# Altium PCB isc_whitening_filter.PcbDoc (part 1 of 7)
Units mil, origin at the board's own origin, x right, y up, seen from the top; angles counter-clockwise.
Board outline 8440 x 7000 mil, 6 copper layers (Top Layer, MidLayer1, InternalPlane1, Internal Plane 3, InternalPlane2, Bottom Layer); 550 components, 434 nets, 2189 pads, 806 vias.
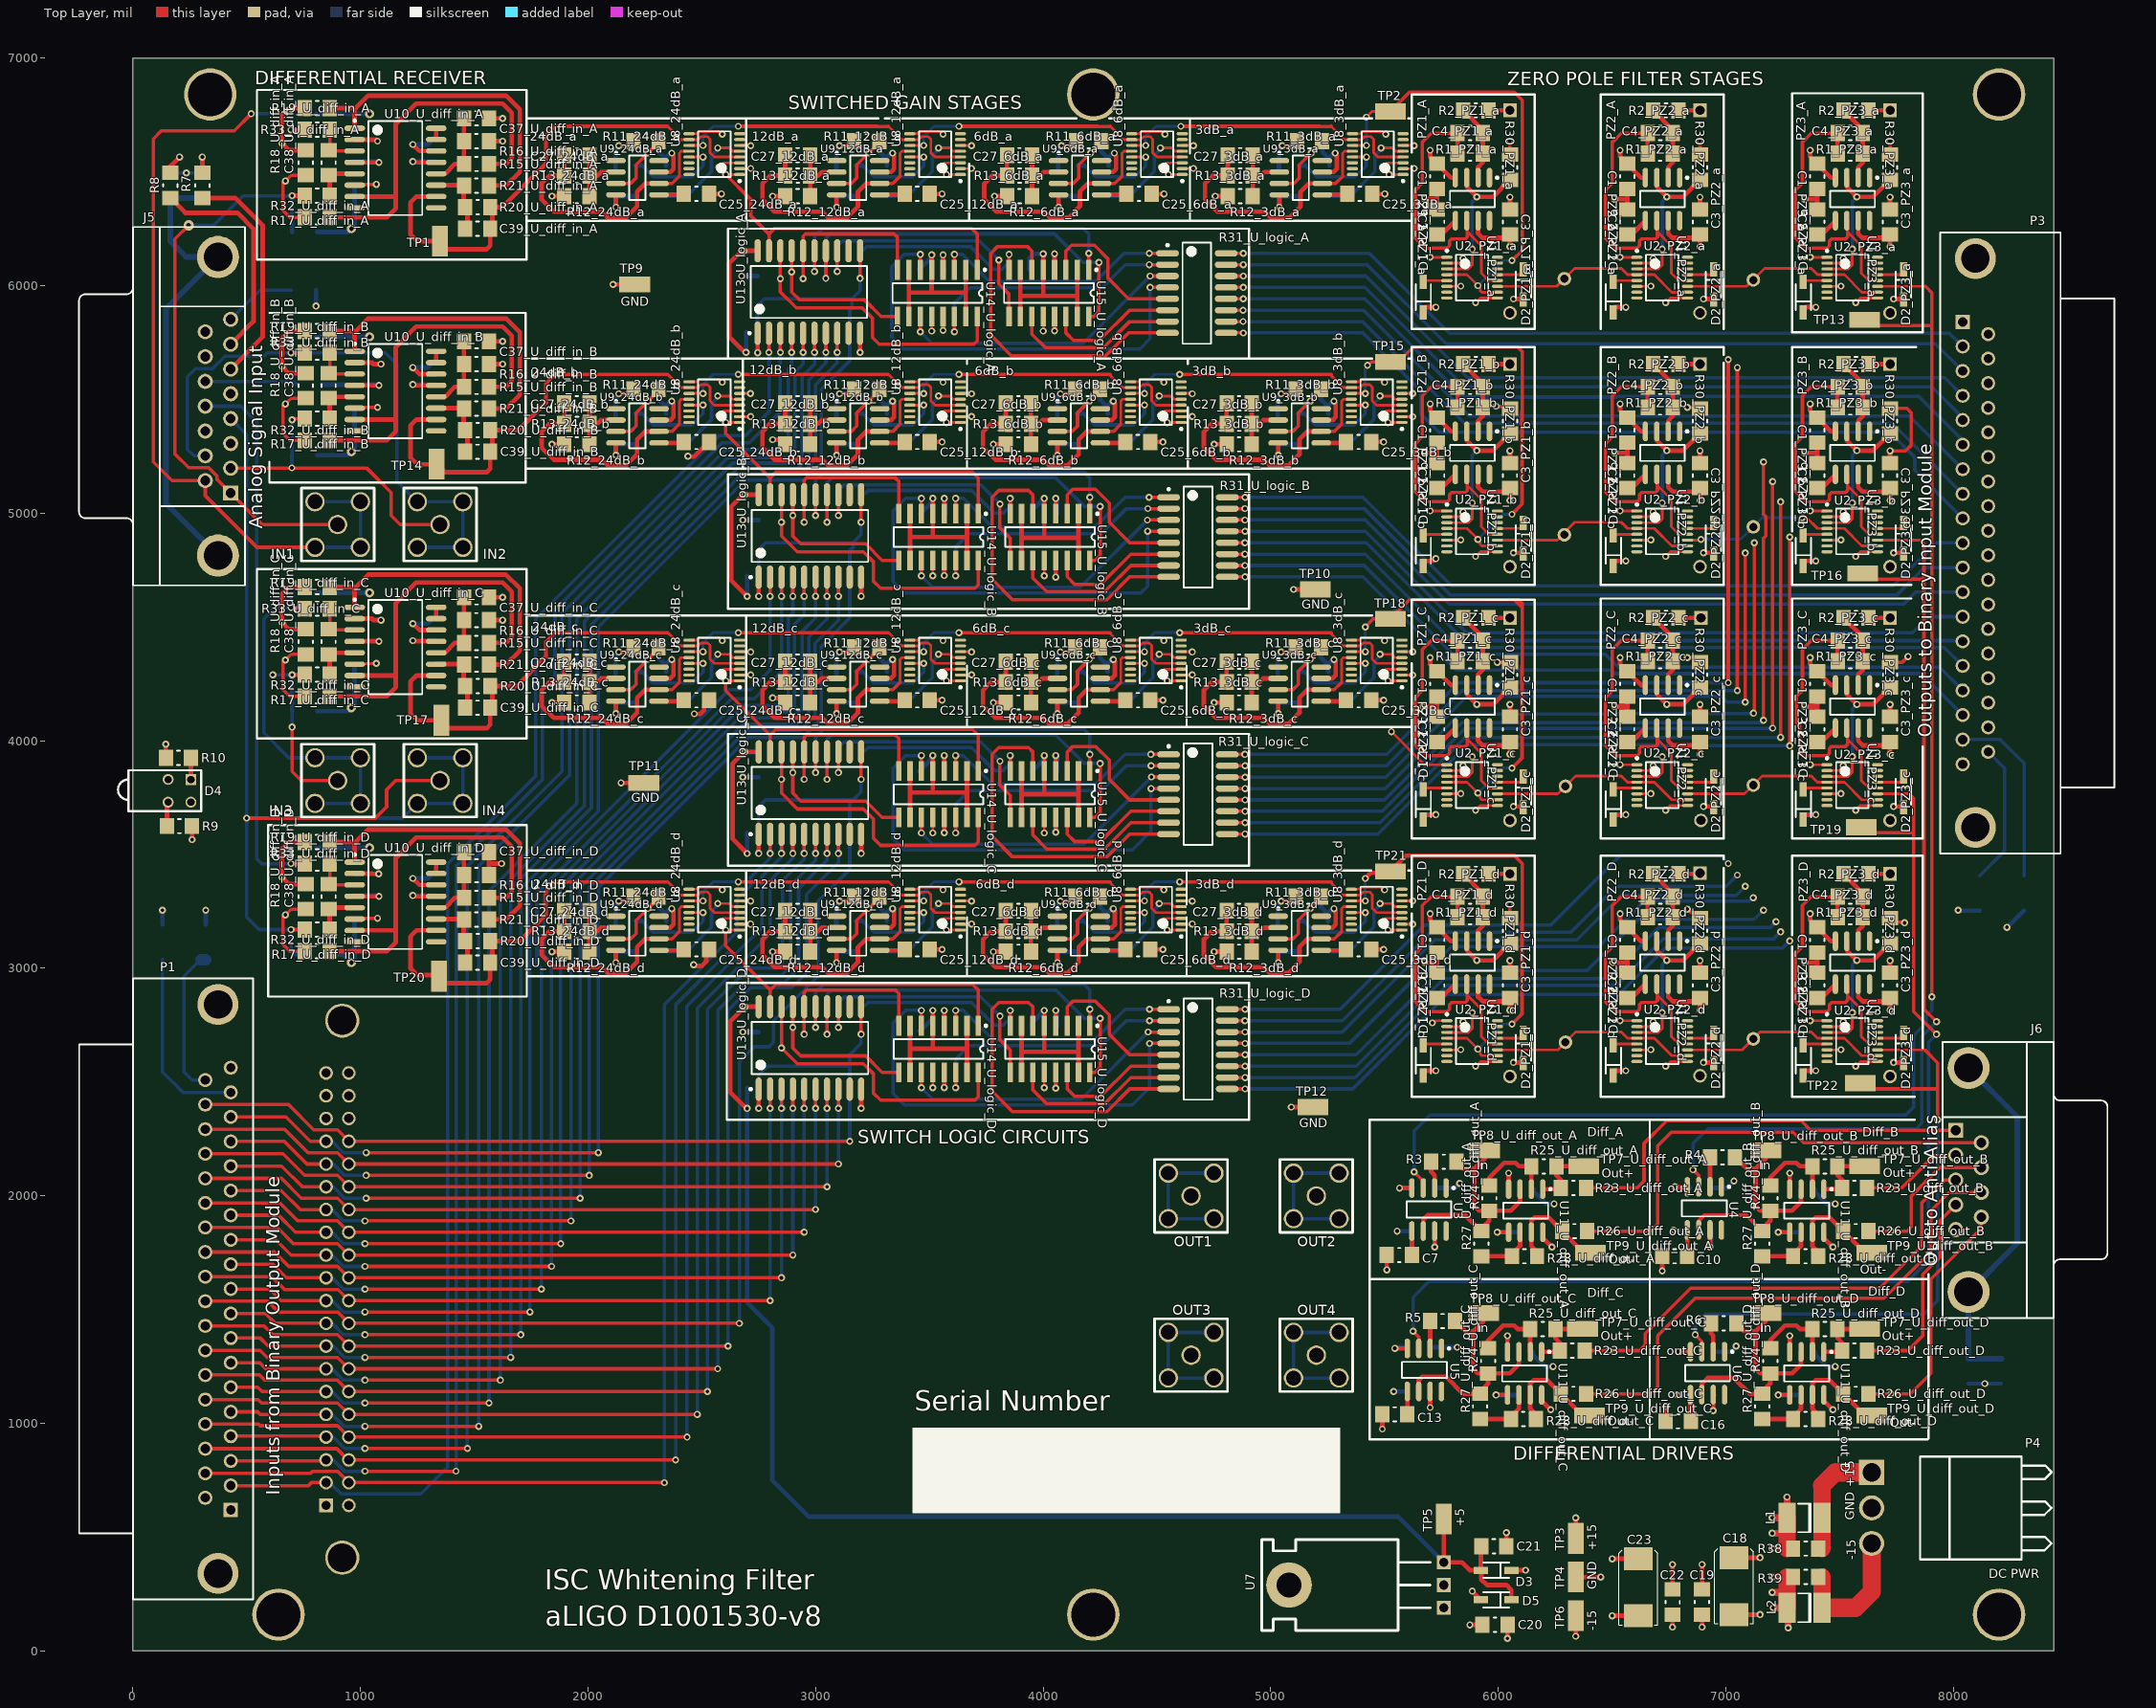
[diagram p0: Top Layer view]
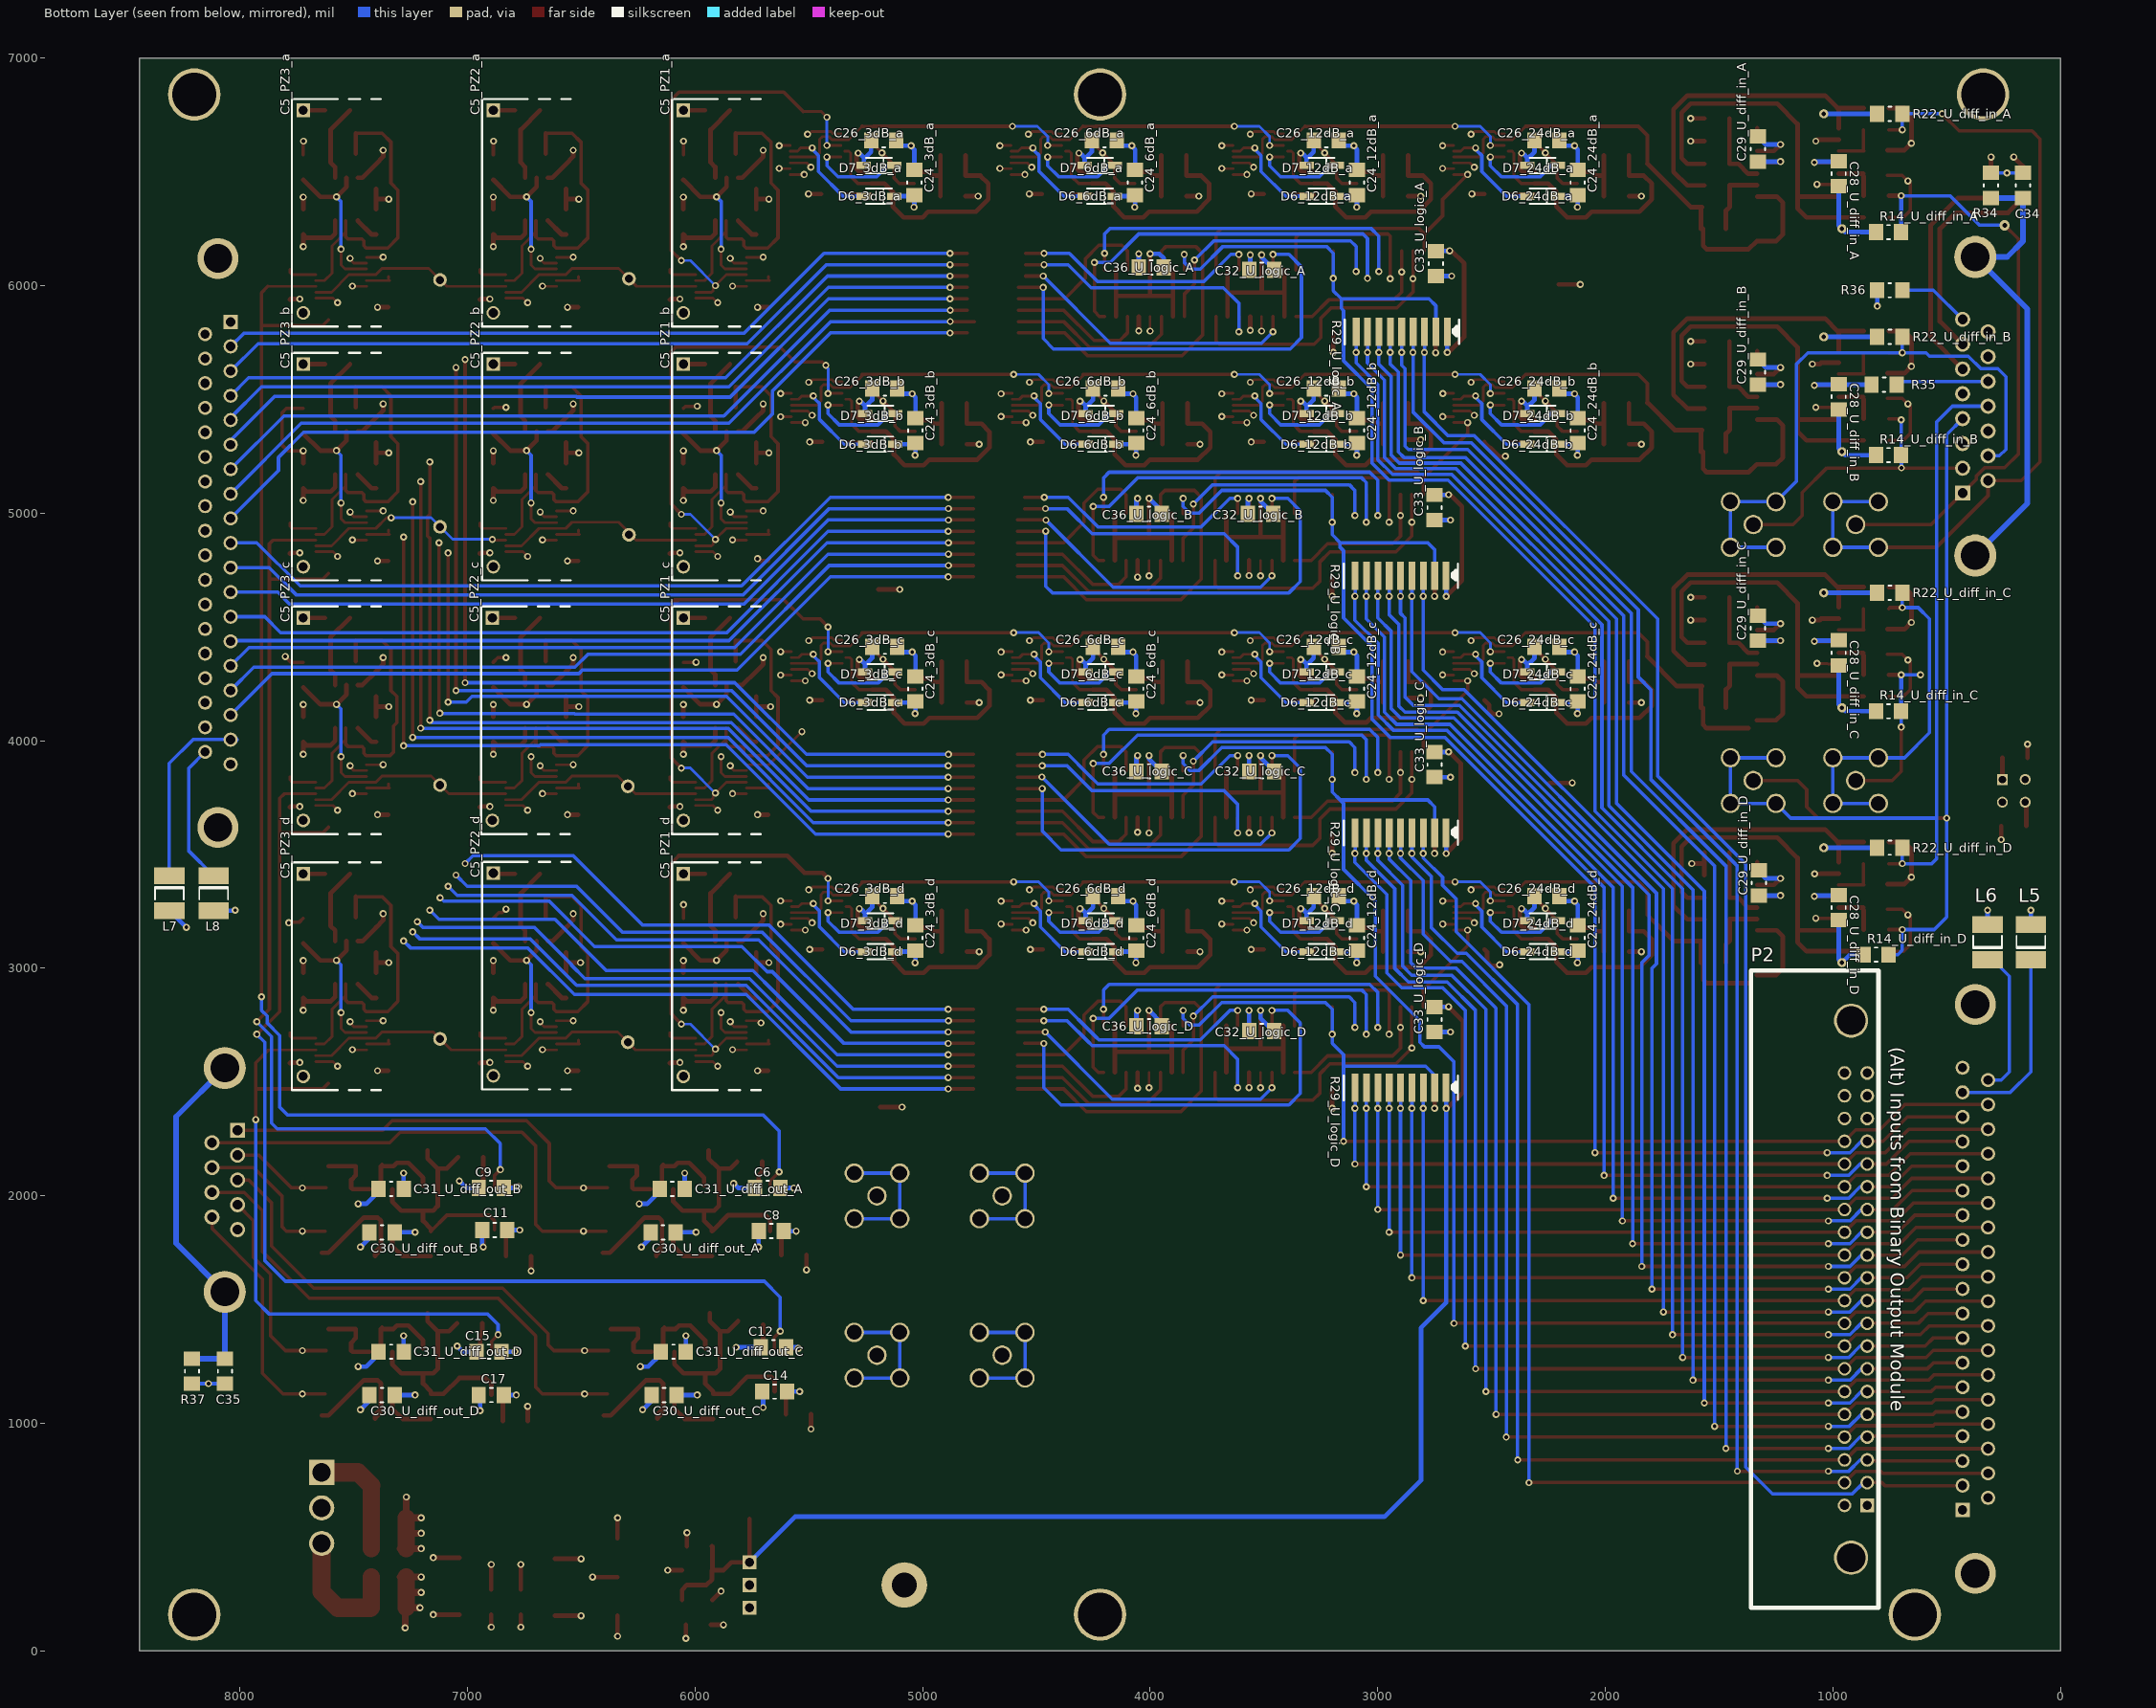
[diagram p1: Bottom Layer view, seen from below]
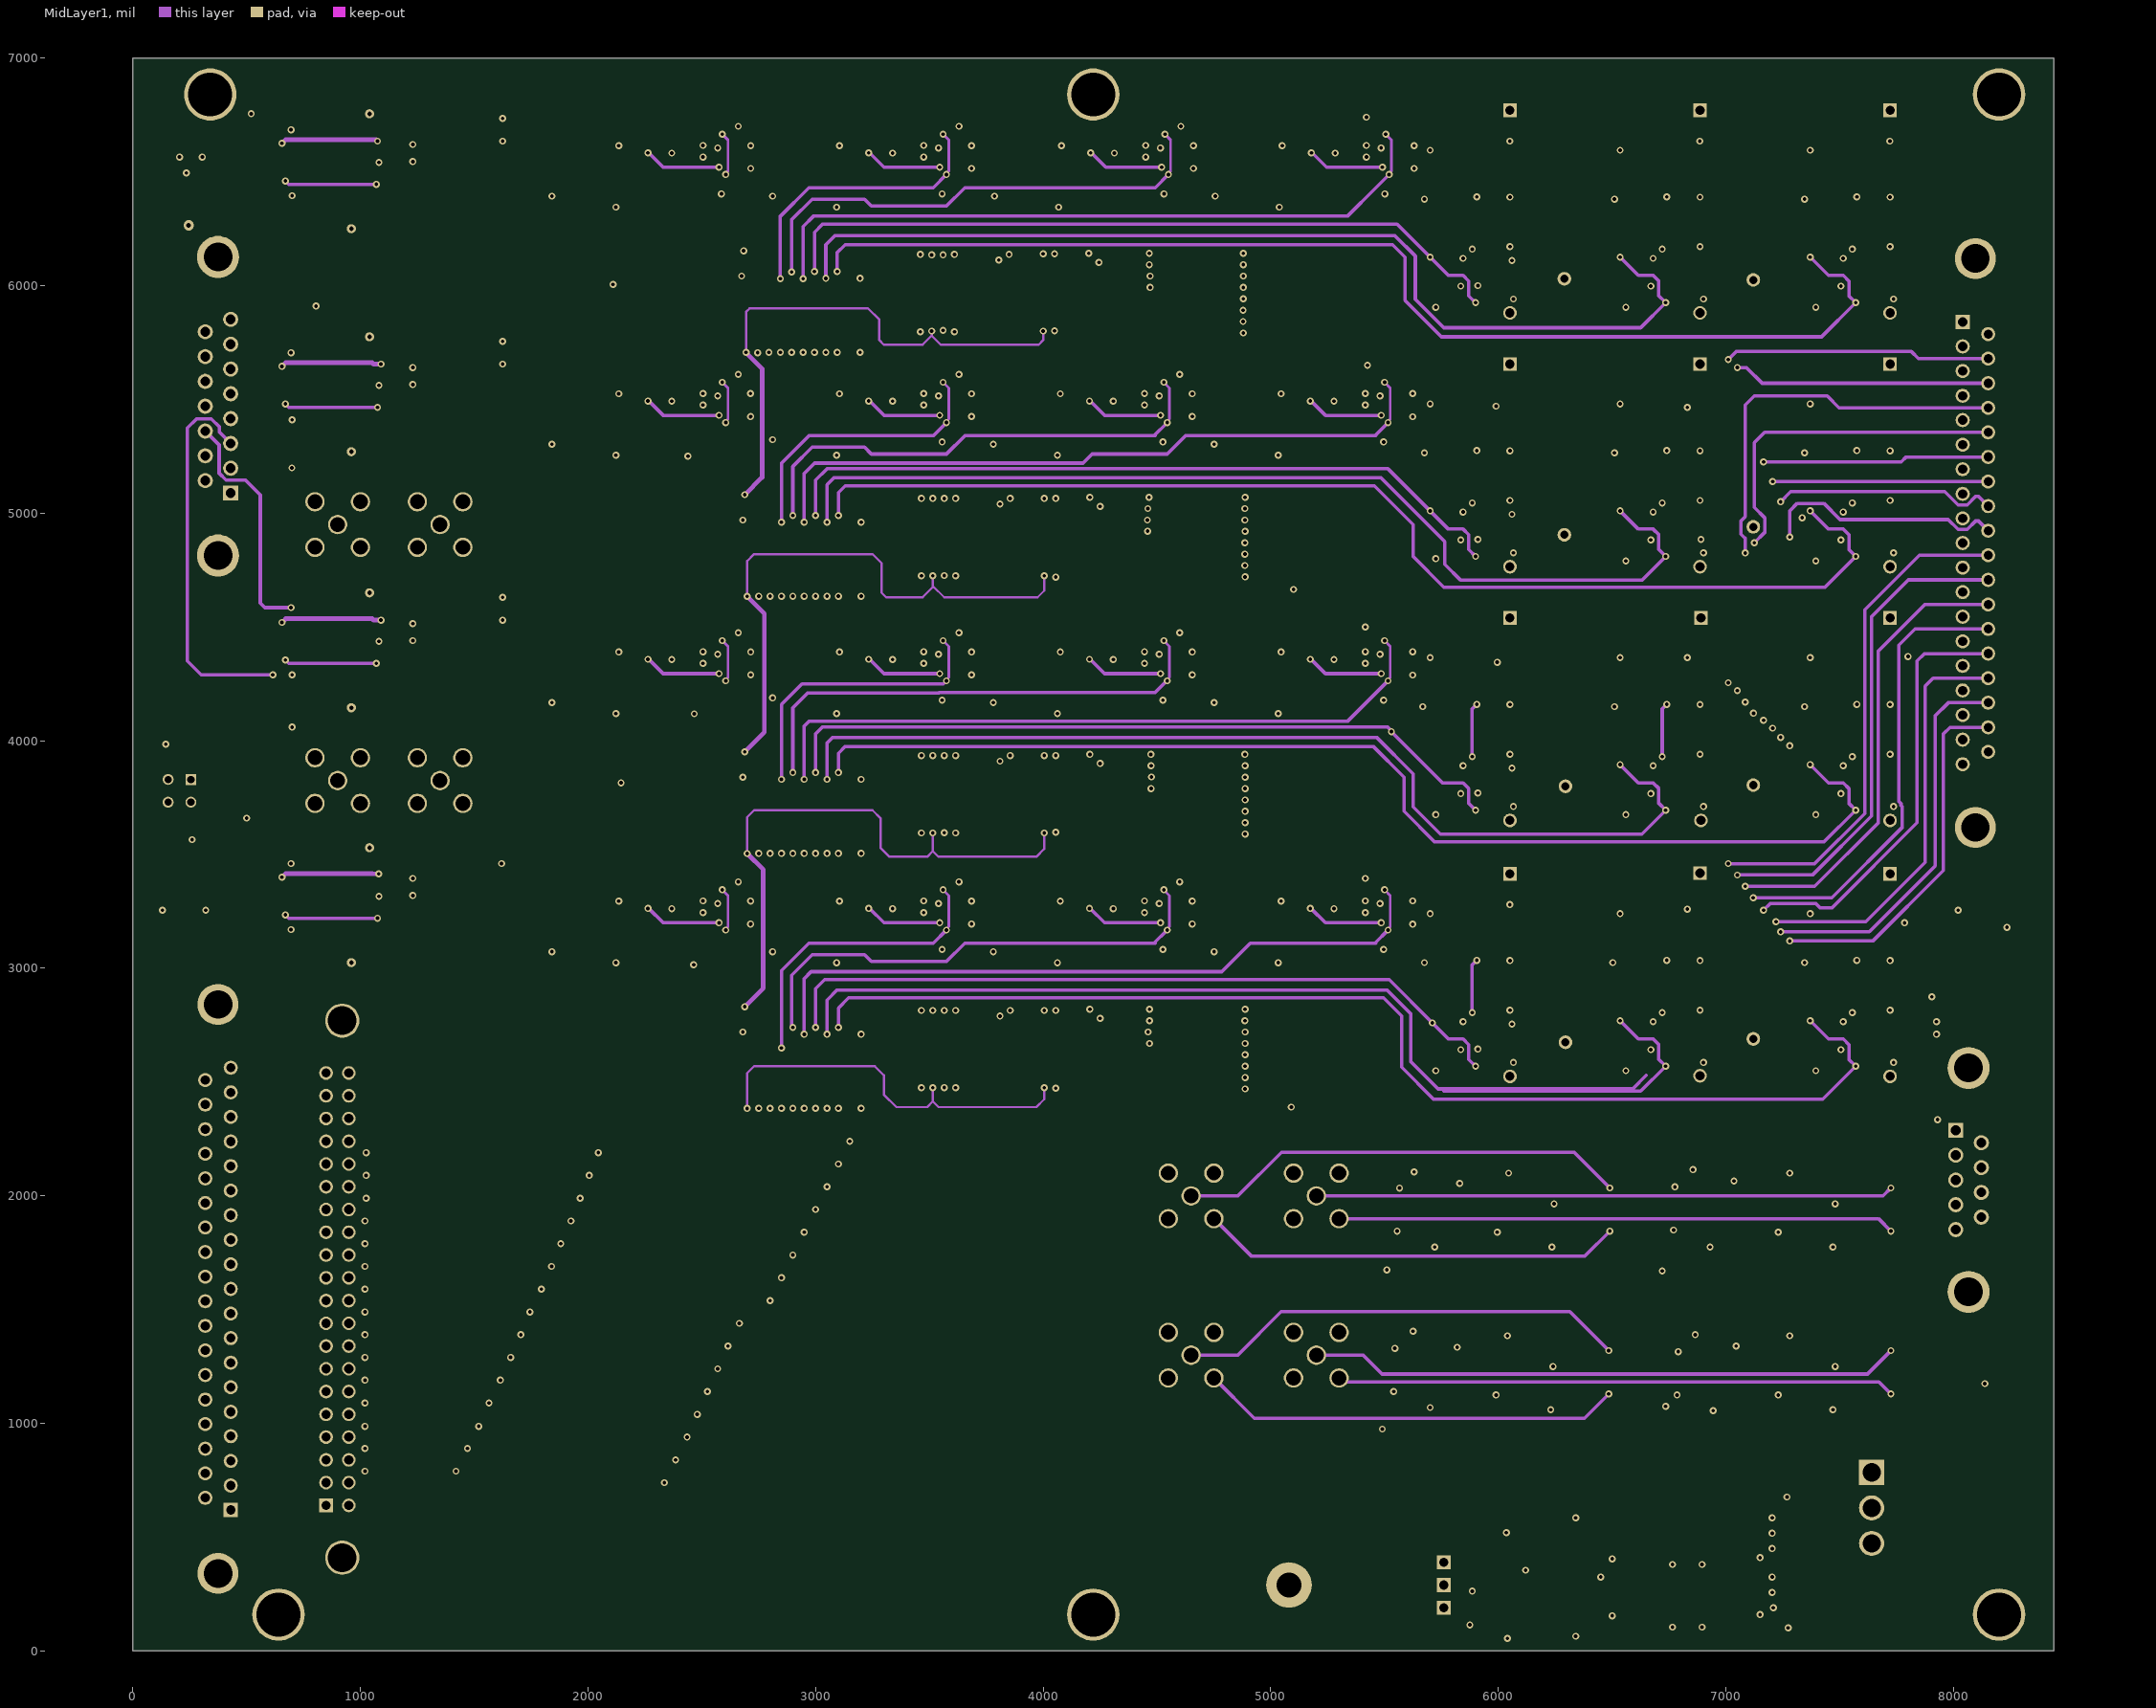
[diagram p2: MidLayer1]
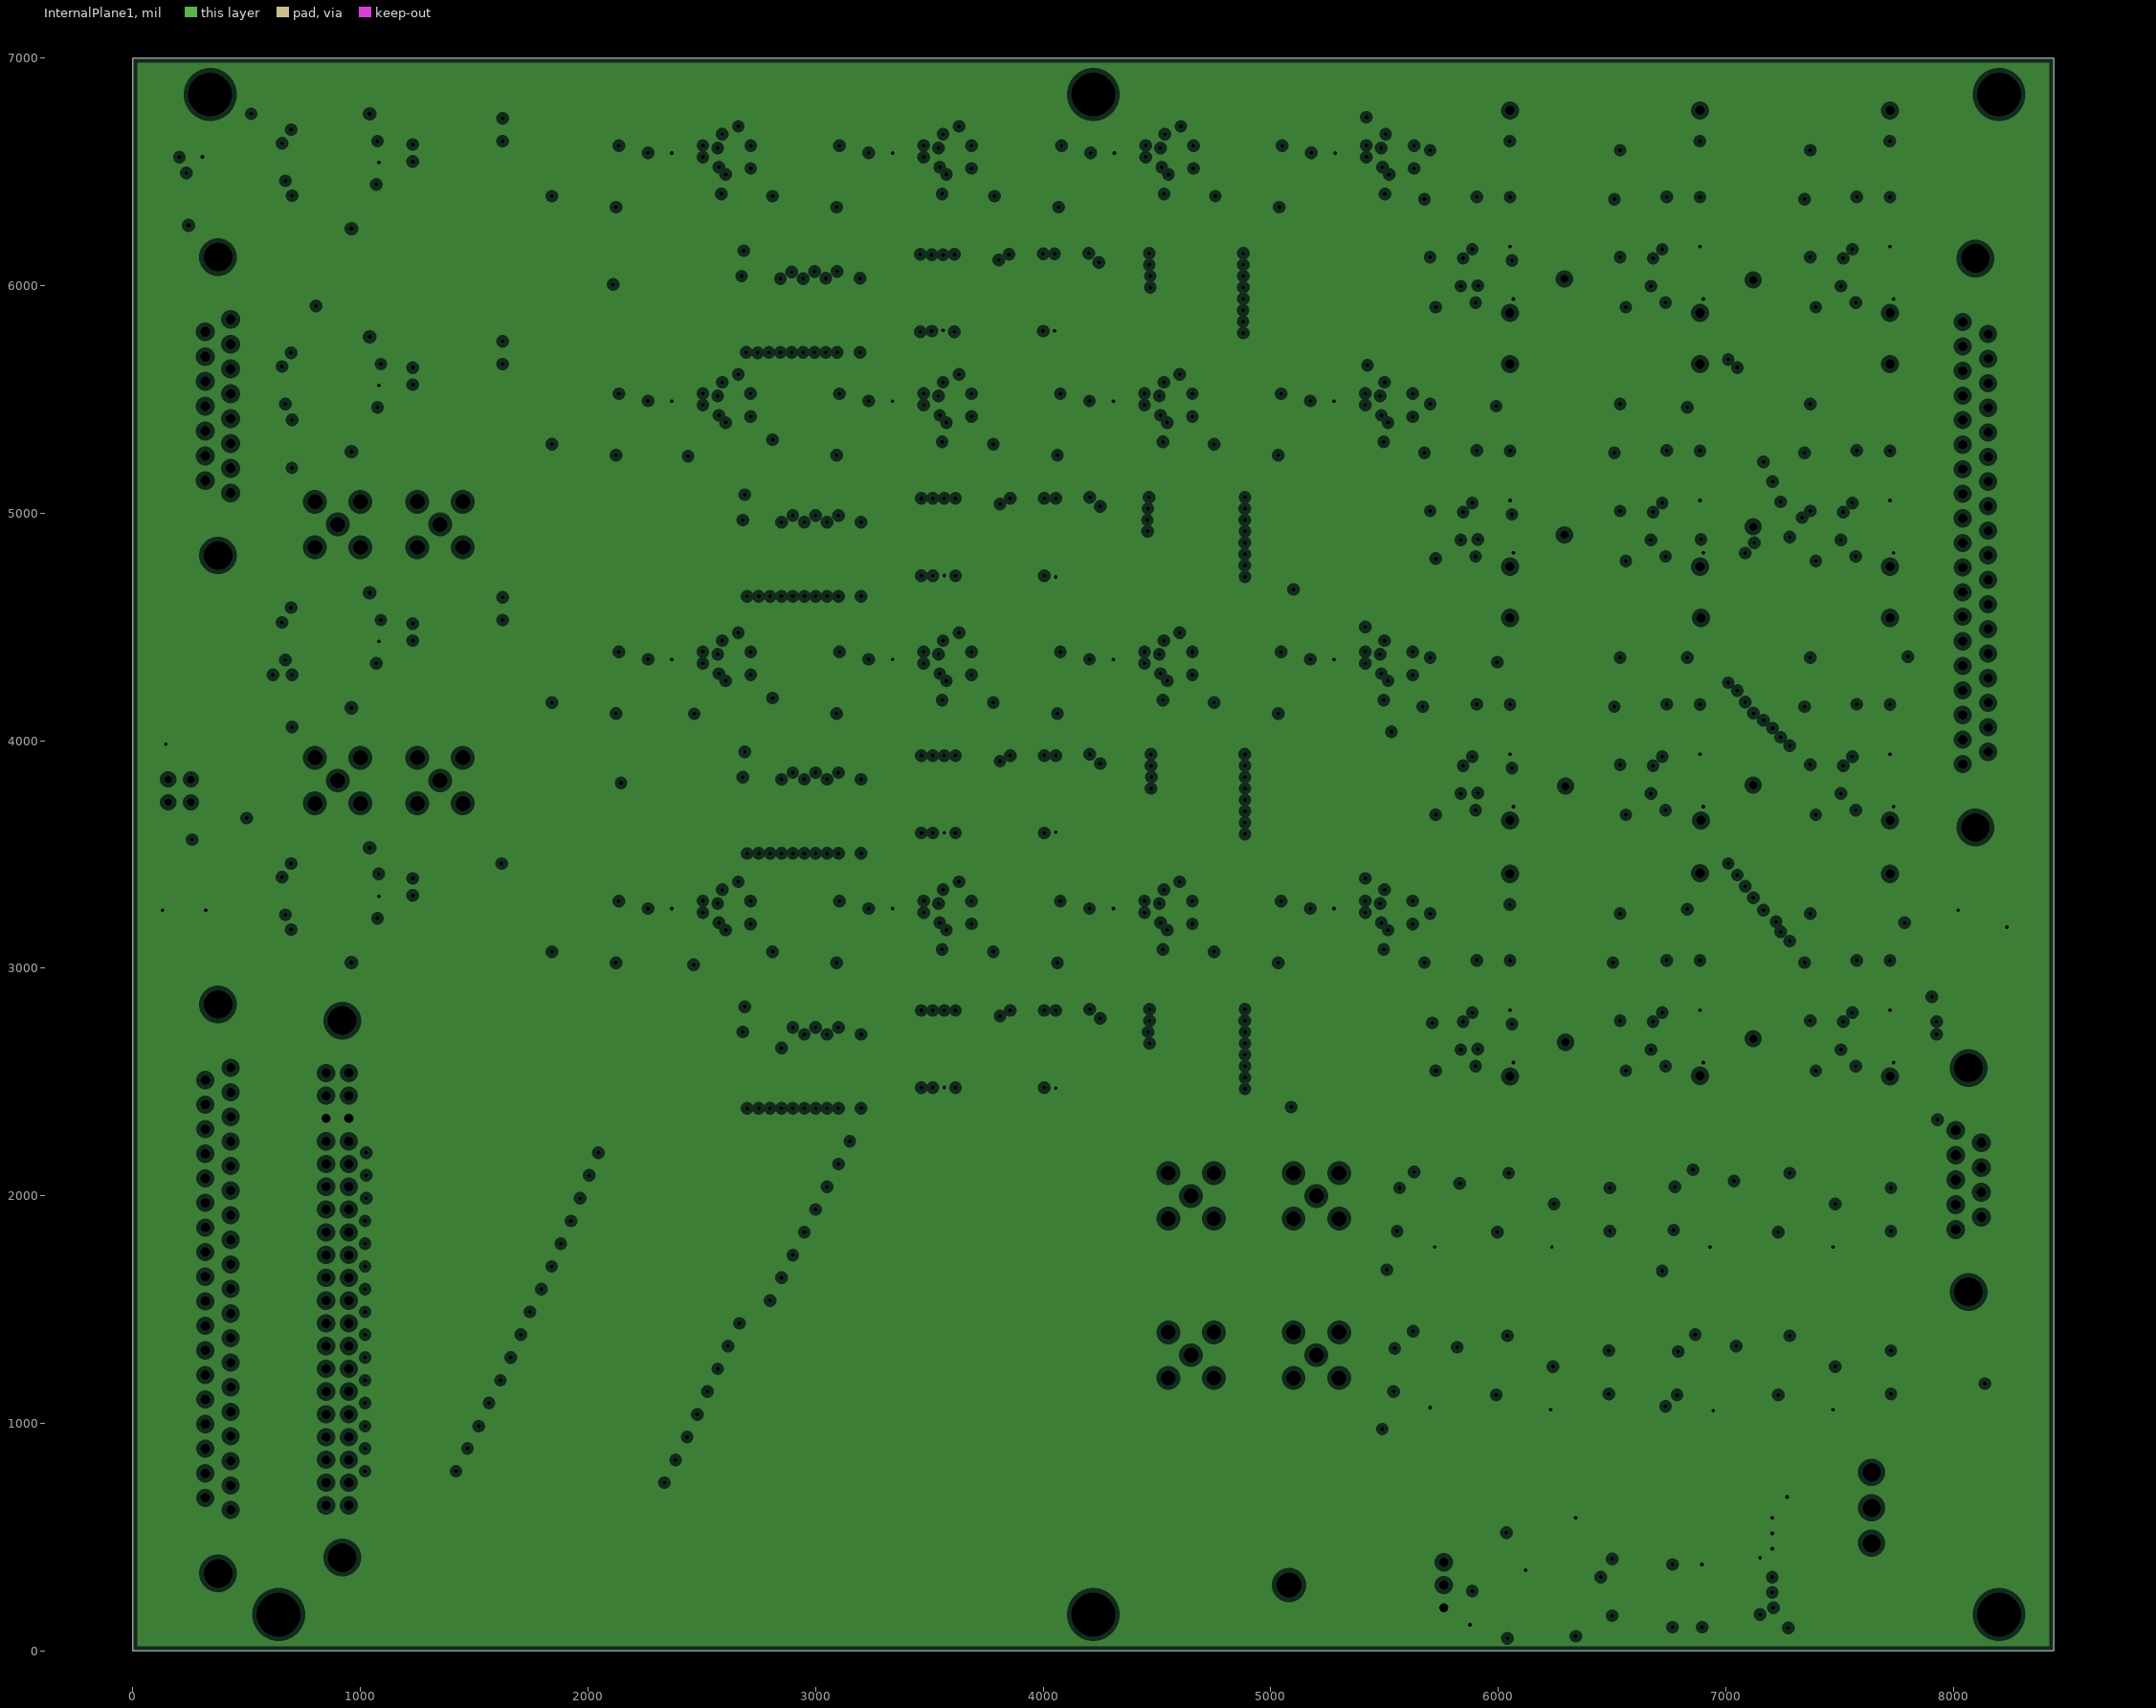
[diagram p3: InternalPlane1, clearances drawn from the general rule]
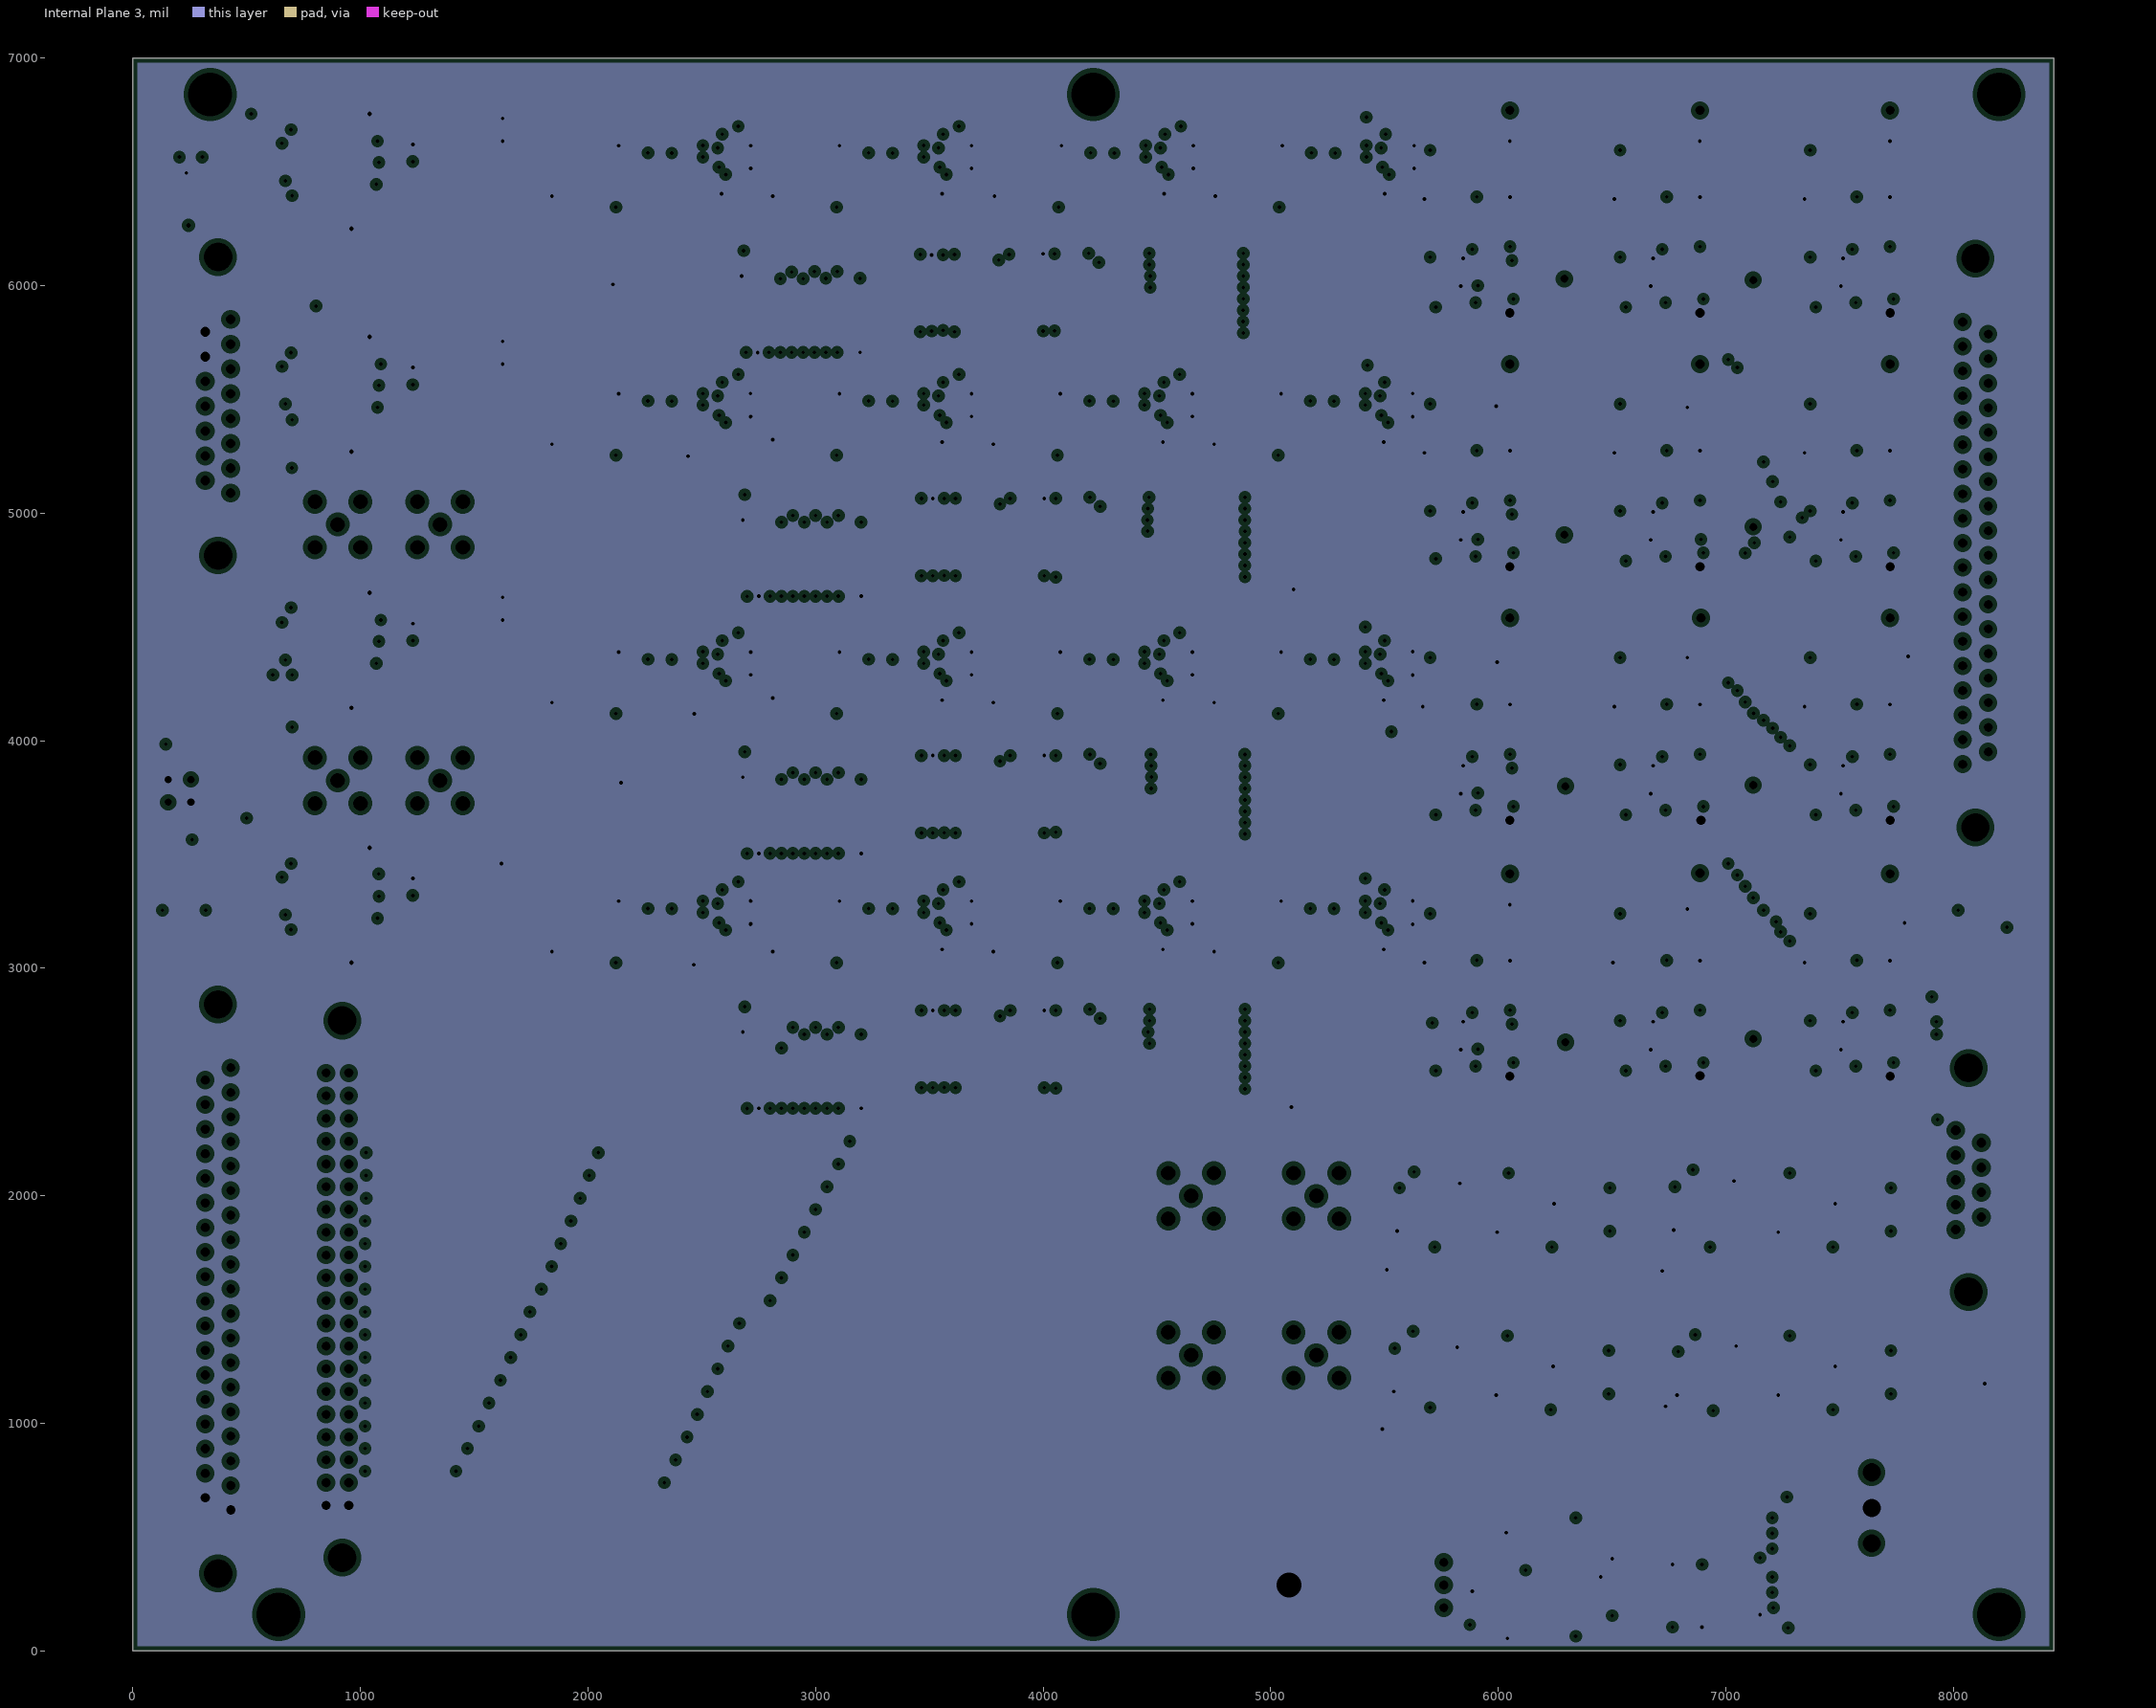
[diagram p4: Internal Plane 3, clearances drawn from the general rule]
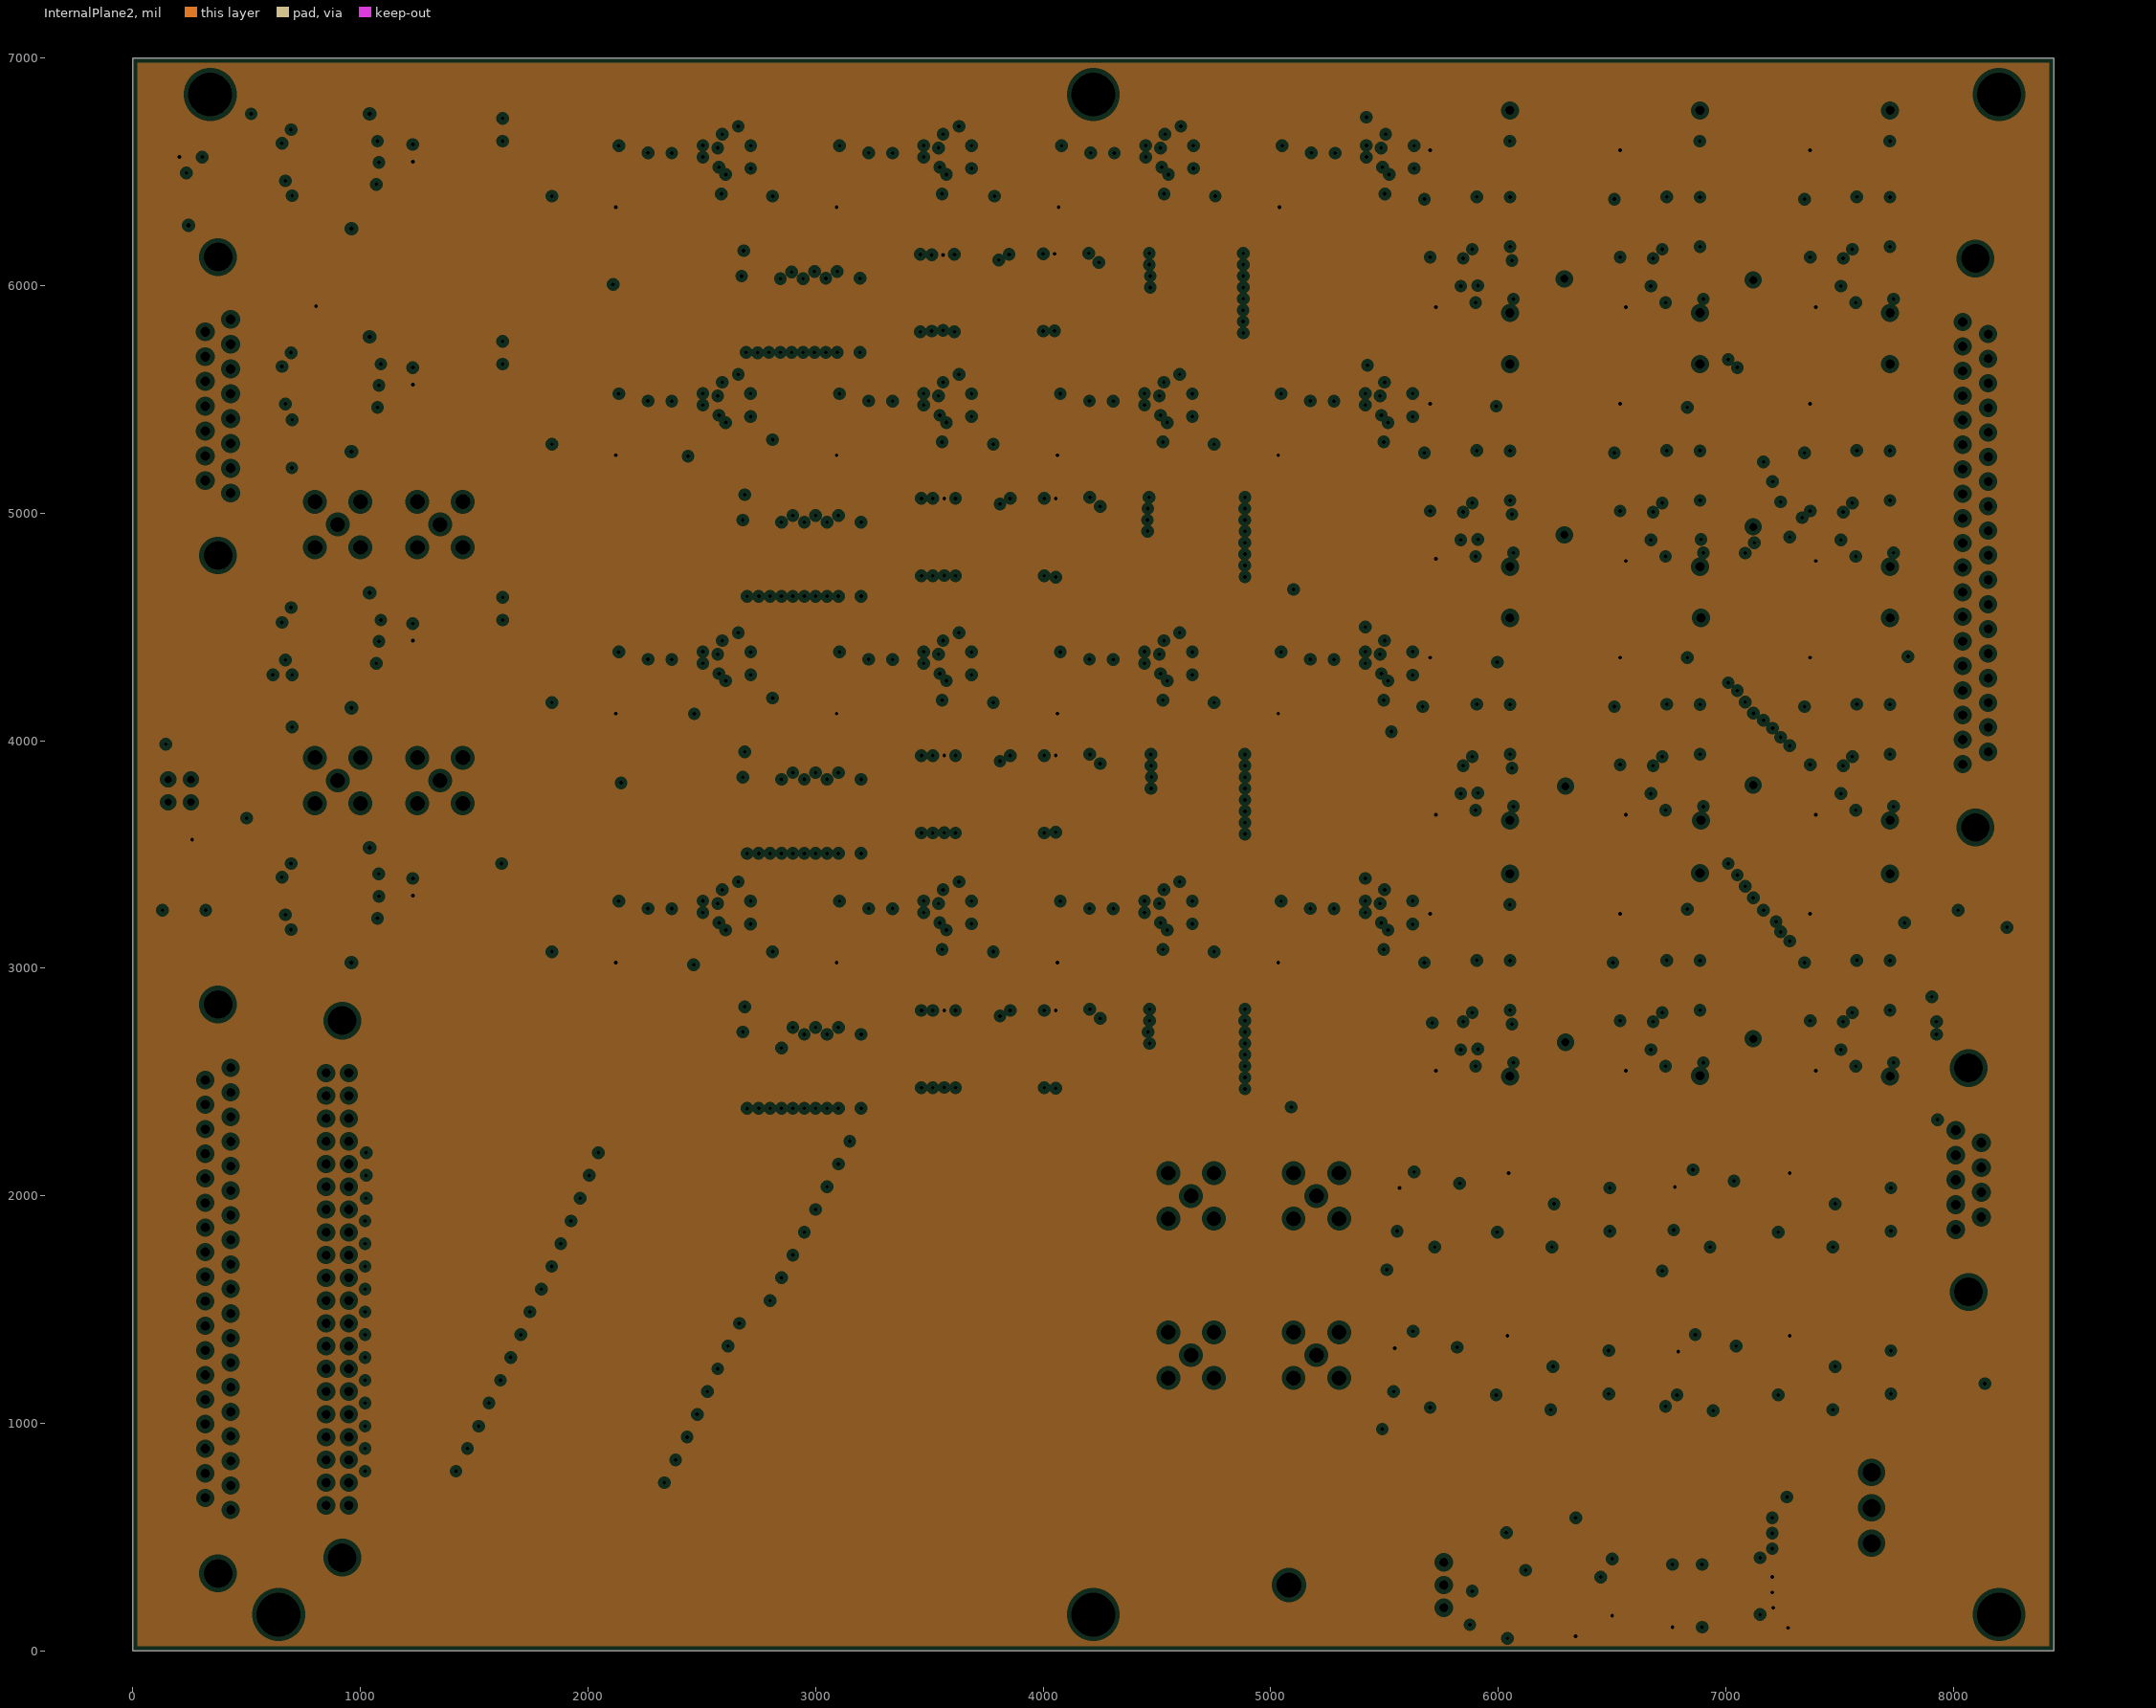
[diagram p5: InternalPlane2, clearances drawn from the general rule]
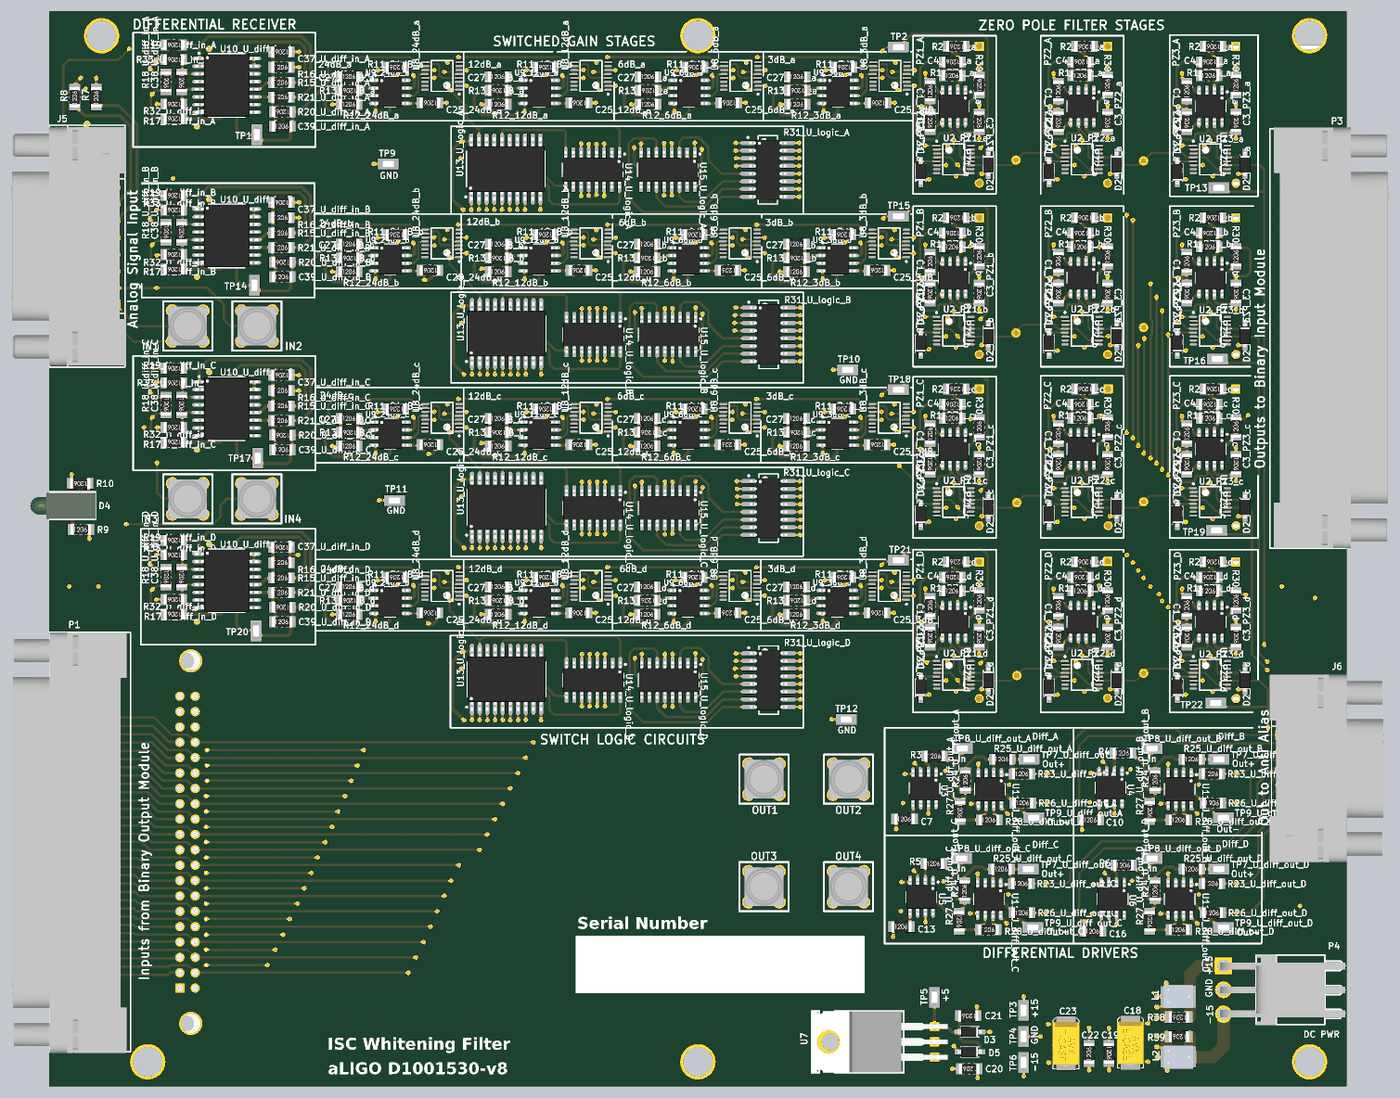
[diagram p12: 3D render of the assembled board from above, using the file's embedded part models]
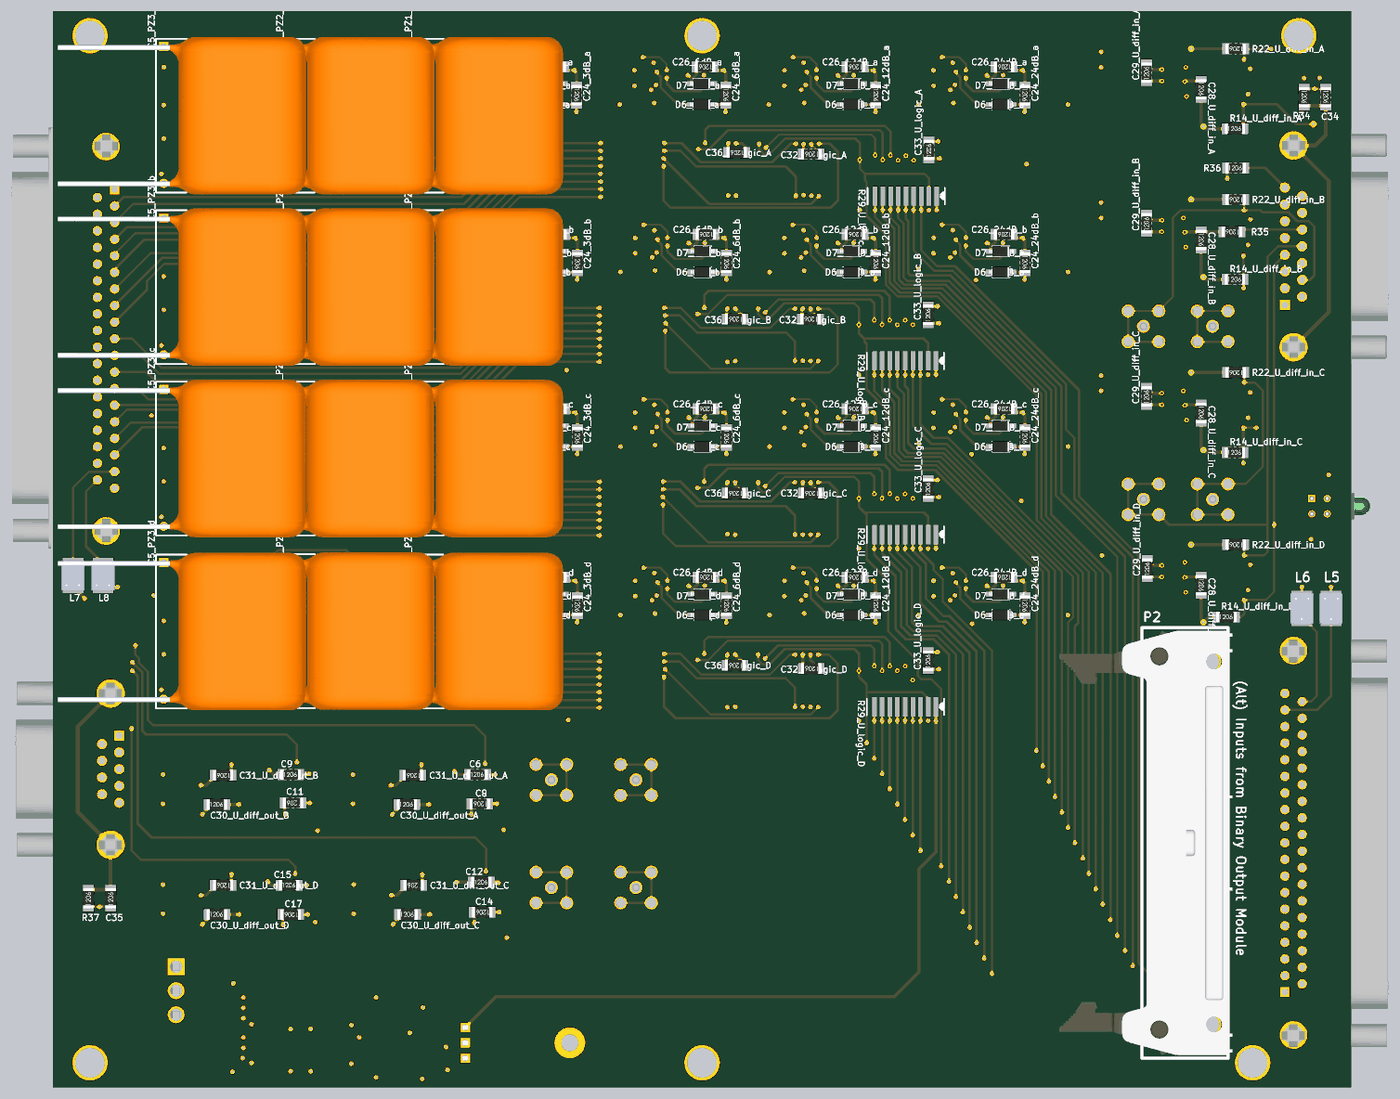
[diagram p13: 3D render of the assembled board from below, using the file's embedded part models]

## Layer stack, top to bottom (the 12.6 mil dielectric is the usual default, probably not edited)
Top Solder: solder mask 0.4, Solder Resist, Dk 3.5
Top Layer: signal copper 1.4
Dielectric1: prepreg 12.6, FR-4, Dk 4.8
MidLayer1: signal copper 1.4
Dielectric2: core 12.6, FR-4, Dk 4.8
InternalPlane1: plane copper 1.4, net +15
Dielectric3: prepreg 12.6, FR-4, Dk 4.8
Internal Plane 3: plane copper 1.4, net GND
Dielectric5: core 12.6, FR-4, Dk 4.8
InternalPlane2: plane copper 1.4, net -15
Dielectric4: prepreg 12.6, FR-4, Dk 4.8
Bottom Layer: signal copper 1.4
Bottom Solder: solder mask 0.4, Solder Resist, Dk 3.5

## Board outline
0,0 8440,0 8440,7000 0,7000

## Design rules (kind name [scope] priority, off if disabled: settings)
Clearance Clearance_1 [(ObjectKind = 'Text') And (TextHeight = AsMils(40)) And (TextWidth = AsMils(7))] p1: gap=10 ignorepadtopadclearanceinfootprint=FALSE
Clearance [All] p2: gap=10 ignorepadtopadclearanceinfootprint=FALSE
DiffPairsRouting DiffPairsRouting_1 [All] p1: maxlimit=10 minlimit=10 mostfreqgap=10 toplayer_minwidth=15 toplayer_maxwidth=15 toplayer_prefwidth=15 midlayer1_minwidth=15 midlayer1_maxwidth=15 midlayer1_prefwidth=15 bottomlayer_minwidth=15 bottomlayer_maxwidth=15 bottomlayer_prefwidth=15 maxuncoupledlength=500
DiffPairsRouting [All] p2: maxlimit=10 minlimit=10 mostfreqgap=10 toplayer_minwidth=15 toplayer_maxwidth=15 toplayer_prefwidth=15 midlayer1_minwidth=15 midlayer1_maxwidth=15 midlayer1_prefwidth=15 bottomlayer_minwidth=15 bottomlayer_maxwidth=15 bottomlayer_prefwidth=15 maxuncoupledlength=500
FabricationTestpoint [(IsPad And (OnTopLayer Or OnBottomLayer))] p1: side=3 testpointundercomponent=TRUE minsize=40 maxsize=100 preferedsize=60 minholesize=0 maxholesize=40 preferedholesize=32 testpointgrid=1 allowsidetop=TRUE allowsidebottom=TRUE usegrid=TRUE gridtolerance=0.01
HoleSize [All] p1: absolutevalues=TRUE maxlimit=200 minlimit=16 maxpercent=80.000 minpercent=20.000
MinimumAnnularRing [All] p1: minimumring=7
PlaneClearance [All] p1: clearance=20
PlaneConnect [All] p1: planeconnectstyle=Relief reliefexpansion=20 reliefentries=4 reliefconductorwidth=10 reliefairgap=10
PolygonConnect [All] p1: connectstyle=Relief reliefconductorwidth=10 reliefentries=4 polygonreliefangle="90 Angle" airgapwidth=10
RoomDefinition 3dB_a [InComponentClass('3dB_a')] p1: confinementstyle=ConfineIn formatcopy=FALSE lockcomponents=FALSE outline 4650,6285 5615,6285 5615,6735 4650,6735
RoomDefinition 3dB_b [InComponentClass('3dB_b')] p2: confinementstyle=ConfineIn formatcopy=TRUE lockcomponents=FALSE outline 4650,5195 5615,5195 5615,5645 4650,5645
RoomDefinition 3dB_c [InComponentClass('3dB_c')] p3: confinementstyle=ConfineIn formatcopy=TRUE lockcomponents=FALSE outline 4650,4060 5615,4060 5615,4510 4650,4510
RoomDefinition 3dB_d [InComponentClass('3dB_d')] p4: confinementstyle=ConfineIn formatcopy=TRUE lockcomponents=FALSE outline 4650,2965 5615,2965 5615,3415 4650,3415
RoomDefinition 6dB_a [InComponentClass('6dB_a')] p5: confinementstyle=ConfineIn formatcopy=FALSE lockcomponents=TRUE outline 3680,6285 4645,6285 4645,6735 3680,6735
RoomDefinition 6dB_b [InComponentClass('6dB_b')] p6: confinementstyle=ConfineIn formatcopy=TRUE lockcomponents=FALSE outline 3680,5195 4645,5195 4645,5645 3680,5645
RoomDefinition 6dB_c [InComponentClass('6dB_c')] p7: confinementstyle=ConfineIn formatcopy=TRUE lockcomponents=FALSE outline 3680,4060 4645,4060 4645,4510 3680,4510
RoomDefinition 6dB_d [InComponentClass('6dB_d')] p8: confinementstyle=ConfineIn formatcopy=TRUE lockcomponents=FALSE outline 3680,2965 4645,2965 4645,3415 3680,3415
RoomDefinition 12dB_a [InComponentClass('12dB_a')] p9: confinementstyle=ConfineIn formatcopy=FALSE lockcomponents=FALSE outline 2710,6285 3675,6285 3675,6735 2710,6735
RoomDefinition 12dB_b [InComponentClass('12dB_b')] p10: confinementstyle=ConfineIn formatcopy=TRUE lockcomponents=FALSE outline 2710,5195 3675,5195 3675,5645 2710,5645
RoomDefinition 12dB_c [InComponentClass('12dB_c')] p11: confinementstyle=ConfineIn formatcopy=TRUE lockcomponents=FALSE outline 2710,4060 3675,4060 3675,4510 2710,4510
RoomDefinition 12dB_d [InComponentClass('12dB_d')] p12: confinementstyle=ConfineIn formatcopy=TRUE lockcomponents=FALSE outline 2710,2965 3675,2965 3675,3415 2710,3415
RoomDefinition 24dB_a [InComponentClass('24dB_a')] p13: confinementstyle=ConfineIn formatcopy=FALSE lockcomponents=FALSE outline 1740,6285 2705,6285 2705,6735 1740,6735
RoomDefinition 24dB_b [InComponentClass('24dB_b')] p14: confinementstyle=ConfineIn formatcopy=FALSE lockcomponents=FALSE outline 1740,5195 2705,5195 2705,5645 1740,5645
RoomDefinition 24dB_c [InComponentClass('24dB_c')] p15: confinementstyle=ConfineIn formatcopy=FALSE lockcomponents=FALSE outline 1740,4060 2705,4060 2705,4510 1740,4510
RoomDefinition 24dB_d [InComponentClass('24dB_d')] p16: confinementstyle=ConfineIn formatcopy=FALSE lockcomponents=FALSE outline 1740,2965 2705,2965 2705,3415 1740,3415
RoomDefinition U_logic_A [InComponentClass('U_logic_A')] p17: confinementstyle=ConfineIn formatcopy=TRUE lockcomponents=FALSE outline 4905,6285 2635,6285 2635,5670 4905,5670
RoomDefinition U_logic_B [InComponentClass('U_logic_B')] p18: confinementstyle=ConfineIn formatcopy=TRUE lockcomponents=FALSE outline 4900,5215 2640,5215 2640,4585 4900,4585
RoomDefinition U_logic_C [InComponentClass('U_logic_C')] p19: confinementstyle=ConfineIn formatcopy=TRUE lockcomponents=FALSE outline 4910,4090 2640,4090 2640,3450 4910,3450
RoomDefinition U_logic_D [InComponentClass('U_logic_D')] p20: confinementstyle=ConfineIn formatcopy=TRUE lockcomponents=FALSE outline 4900,2955 2640,2955 2640,2340 4900,2340
RoomDefinition U_diff_out_A [InComponentClass('U_diff_out_A')] p21: confinementstyle=ConfineIn formatcopy=TRUE lockcomponents=FALSE outline 5855,1690 6590,1690 6590,2245 5855,2245
RoomDefinition U_diff_out_B [InComponentClass('U_diff_out_B')] p22: confinementstyle=ConfineIn formatcopy=TRUE lockcomponents=FALSE outline 7090,1690 7825,1690 7825,2250 7090,2250
RoomDefinition U_diff_out_C [InComponentClass('U_diff_out_C')] p23: confinementstyle=ConfineIn formatcopy=TRUE lockcomponents=FALSE outline 5850,975 6585,975 6585,1535 5850,1535
RoomDefinition U_diff_out_D [InComponentClass('U_diff_out_D')] p24: confinementstyle=ConfineIn formatcopy=TRUE lockcomponents=FALSE outline 7090,975 7825,975 7825,1530 7090,1530
RoomDefinition U_diff_in_A [InComponentClass('U_diff_in_A')] p25: confinementstyle=ConfineIn formatcopy=TRUE lockcomponents=FALSE outline 600,6115 1725,6115 1725,6860 600,6860
RoomDefinition U_diff_in_B [InComponentClass('U_diff_in_B')] p26: confinementstyle=ConfineIn formatcopy=TRUE lockcomponents=FALSE outline 600,5135 1725,5135 1725,5880 600,5880
RoomDefinition U_diff_in_C [InComponentClass('U_diff_in_C')] p27: confinementstyle=ConfineIn formatcopy=TRUE lockcomponents=FALSE outline 600,4010 1725,4010 1725,4755 600,4755
RoomDefinition U_diff_in_D [InComponentClass('U_diff_in_D')] p28: confinementstyle=ConfineIn formatcopy=TRUE lockcomponents=FALSE outline 600,2890 1725,2890 1725,3635 600,3635
RoomDefinition PZ1_a [InComponentClass('PZ1_a') and not HasFootprint('ECQ-E1106KF_Side')] p29: confinementstyle=ConfineIn formatcopy=TRUE lockcomponents=FALSE outline 5620,5800 6150,5800 6150,6840 5620,6840
RoomDefinition PZ1_b [InComponentClass('PZ1_b') and not HasFootprint('ECQ-E1106KF_Side')] p30: confinementstyle=ConfineIn formatcopy=TRUE lockcomponents=FALSE outline 5620,4685 6150,4685 6150,5725 5620,5725
RoomDefinition PZ1_c [InComponentClass('PZ1_c') and not HasFootprint('ECQ-E1106KF_Side')] p31: confinementstyle=ConfineIn formatcopy=TRUE lockcomponents=FALSE outline 5620,3570 6150,3570 6150,4610 5620,4610
RoomDefinition PZ1_d [InComponentClass('PZ1_d') and not HasFootprint('ECQ-E1106KF_Side')] p32: confinementstyle=ConfineIn formatcopy=TRUE lockcomponents=FALSE outline 5620,2445 6150,2445 6150,3485 5620,3485
RoomDefinition PZ2_a [InComponentClass('PZ2_a') and not HasFootprint('ECQ-E1106KF_Side')] p33: confinementstyle=ConfineIn formatcopy=TRUE lockcomponents=FALSE outline 6455,5800 6985,5800 6985,6840 6455,6840
RoomDefinition PZ2_b [InComponentClass('PZ2_b') and not HasFootprint('ECQ-E1106KF_Side')] p34: confinementstyle=ConfineIn formatcopy=TRUE lockcomponents=FALSE outline 6455,4685 6985,4685 6985,5725 6455,5725
RoomDefinition PZ2_c [InComponentClass('PZ2_c') and not HasFootprint('ECQ-E1106KF_Side')] p35: confinementstyle=ConfineIn formatcopy=TRUE lockcomponents=FALSE outline 6455,3570 6985,3570 6985,4610 6455,4610
RoomDefinition PZ2_d [InComponentClass('PZ2_d') and not HasFootprint('ECQ-E1106KF_Side')] p36: confinementstyle=ConfineIn formatcopy=TRUE lockcomponents=FALSE outline 6455,2445 6985,2445 6985,3485 6455,3485
RoomDefinition PZ3_a [InComponentClass('PZ3_a') and not HasFootprint('ECQ-E1106KF_Side')] p37: confinementstyle=ConfineIn formatcopy=TRUE lockcomponents=FALSE outline 7290,5800 7820,5800 7820,6840 7290,6840
RoomDefinition PZ3_b [InComponentClass('PZ3_b') and not HasFootprint('ECQ-E1106KF_Side')] p38: confinementstyle=ConfineIn formatcopy=TRUE lockcomponents=FALSE outline 7290,4685 7820,4685 7820,5725 7290,5725
RoomDefinition PZ3_c [InComponentClass('PZ3_c') and not HasFootprint('ECQ-E1106KF_Side')] p39: confinementstyle=ConfineIn formatcopy=TRUE lockcomponents=FALSE outline 7290,3570 7820,3570 7820,4610 7290,4610
RoomDefinition PZ3_d [InComponentClass('PZ3_d') and not HasFootprint('ECQ-E1106KF_Side')] p40: confinementstyle=ConfineIn formatcopy=TRUE lockcomponents=FALSE outline 7290,2445 7820,2445 7820,3485 7290,3485
RoutingVias [All] p1: holewidth=16 width=31 viastyle="Through Hole" minholewidth=16 minwidth=31 maxholewidth=16 maxwidth=31
SilkToSolderMaskClearance SilkscreenOverComponentPads [IsPad] p1: minsilkscreentomaskgap=10 clearancetoexposedcopper=TRUE
SolderMaskExpansion [All] p1: expansion=4 istentingtop=FALSE
SupplyNets "Schematic Supply Nets_3" [InNet('GND')] p1: voltage=0.000
SupplyNets "Schematic Supply Nets_2" [InNet('-15')] p2: voltage=0.000
SupplyNets "Schematic Supply Nets_1" [InNet('+15')] p3: voltage=0.000
SupplyNets "Schematic Supply Nets" [InNet('VCC')] p4: voltage=0.000
Width [All] p1: maxlimit=100 minlimit=9 preferedwidth=15
24 further rules are at their usual default settings.

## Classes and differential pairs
net class R39_Nets: -15 NetL2_1
net class R38_Nets: +15 NetL1_1
net class OUT4_Nets: WN4 WP4
net class OUT3_Nets: WN3 WP3
net class OUT2_Nets: WN2 WP2
net class OUT1_Nets: WN1 WP1
net class R37_Nets: GND NetC35_2
net class R36_Nets: -15 NetJ5_8
net class R35_Nets: +15 NetJ5_13
net class R34_Nets: GND NetC34_2
net class IN4_Nets: AN_4 AP_4
net class IN3_Nets: AN_3 AP_3
net class IN2_Nets: AN_2 AP_2
net class IN1_Nets: AN_1 AP_1
net class C35_Nets: GND NetC35_2
net class C34_Nets: GND NetC34_2
net class U15_U_logic_D_Nets: +15 -15 BI_31 D5 D6 D7 GND NetR31_U_logic_D_5 NetR31_U_logic_D_6 NetR31_U_logic_D_7 NetR31_U_logic_D_8 VCC
net class U15_U_logic_C_Nets: +15 -15 BI_23 C5 C6 C7 GND NetR31_U_logic_C_5 NetR31_U_logic_C_6 NetR31_U_logic_C_7 NetR31_U_logic_C_8 VCC
net class U15_U_logic_B_Nets: +15 -15 B5 B6 B7 BI_15 GND NetR31_U_logic_B_5 NetR31_U_logic_B_6 NetR31_U_logic_B_7 NetR31_U_logic_B_8 VCC
net class U15_U_logic_A_Nets: +15 -15 A5 A6 A7 BI_7 GND NetR31_U_logic_A_5 NetR31_U_logic_A_6 NetR31_U_logic_A_7 NetR31_U_logic_A_8 VCC
net class U14_U_logic_D_Nets: +15 -15 D1 D2 D3 D4 GND NetR31_U_logic_D_1 NetR31_U_logic_D_2 NetR31_U_logic_D_3 NetR31_U_logic_D_4 VCC
net class U14_U_logic_C_Nets: +15 -15 C1 C2 C3 C4 GND NetR31_U_logic_C_1 NetR31_U_logic_C_2 NetR31_U_logic_C_3 NetR31_U_logic_C_4 VCC
net class U14_U_logic_B_Nets: +15 -15 B1 B2 B3 B4 GND NetR31_U_logic_B_1 NetR31_U_logic_B_2 NetR31_U_logic_B_3 NetR31_U_logic_B_4 VCC
net class U14_U_logic_A_Nets: +15 -15 A1 A2 A3 A4 GND NetR31_U_logic_A_1 NetR31_U_logic_A_2 NetR31_U_logic_A_3 NetR31_U_logic_A_4 VCC
net class U13_U_logic_D_Nets: BI_24 BI_25 BI_26 BI_27 BI_28 BI_29 BI_30 BI_31 D1 D2 D3 D4 D5 D6 D7 GND NetU13_U_logic_D_9 NetU13_U_logic_D_12 VCC
net class U13_U_logic_C_Nets: BI_16 BI_17 BI_18 BI_19 BI_20 BI_21 BI_22 BI_23 C1 C2 C3 C4 C5 C6 C7 GND NetU13_U_logic_C_9 NetU13_U_logic_C_12 VCC
net class U13_U_logic_B_Nets: B1 B2 B3 B4 B5 B6 B7 BI_8 BI_9 BI_10 BI_11 BI_12 BI_13 BI_14 BI_15 GND NetU13_U_logic_B_9 NetU13_U_logic_B_12 VCC
net class U13_U_logic_A_Nets: A1 A2 A3 A4 A5 A6 A7 BI_0 BI_1 BI_2 BI_3 BI_4 BI_5 BI_6 BI_7 GND NetU13_U_logic_A_9 NetU13_U_logic_A_12 VCC
net class U11_U_diff_out_D_Nets: +15 -15 GND NetR6_2 NetR23_U_diff_out_D_1 NetR24_U_diff_out_D_2 NetR26_U_diff_out_D_1 NetR27_U_diff_out_D_2 NetU11_U_diff_out_D_4 NetU11_U_diff_out_D_8
net class U11_U_diff_out_C_Nets: +15 -15 GND NetR5_2 NetR23_U_diff_out_C_1 NetR24_U_diff_out_C_2 NetR26_U_diff_out_C_1 NetR27_U_diff_out_C_2 NetU11_U_diff_out_C_4 NetU11_U_diff_out_C_8
net class U11_U_diff_out_B_Nets: +15 -15 GND NetR4_2 NetR23_U_diff_out_B_1 NetR24_U_diff_out_B_2 NetR26_U_diff_out_B_1 NetR27_U_diff_out_B_2 NetU11_U_diff_out_B_4 NetU11_U_diff_out_B_8
net class U11_U_diff_out_A_Nets: +15 -15 GND NetR3_2 NetR23_U_diff_out_A_1 NetR24_U_diff_out_A_2 NetR26_U_diff_out_A_1 NetR27_U_diff_out_A_2 NetU11_U_diff_out_A_4 NetU11_U_diff_out_A_8
net class U10_U_diff_in_D_Nets: +15 -15 GND NetC37_U_diff_in_D_2 NetC38_U_diff_in_D_1 NetC38_U_diff_in_D_2 NetC39_U_diff_in_D_1 NetC39_U_diff_in_D_2 NetR15_U_diff_in_D_2 NetR17_U_diff_in_D_2 NetR18_U_diff_in_D_1 NetR19_U_diff_in_D_1 NetU10_U_diff_in_D_15
net class U10_U_diff_in_C_Nets: +15 -15 GND NetC37_U_diff_in_C_2 NetC38_U_diff_in_C_1 NetC38_U_diff_in_C_2 NetC39_U_diff_in_C_1 NetC39_U_diff_in_C_2 NetR15_U_diff_in_C_2 NetR17_U_diff_in_C_2 NetR18_U_diff_in_C_1 NetR19_U_diff_in_C_1 NetU10_U_diff_in_C_15
net class U10_U_diff_in_B_Nets: +15 -15 GND NetC37_U_diff_in_B_2 NetC38_U_diff_in_B_1 NetC38_U_diff_in_B_2 NetC39_U_diff_in_B_1 NetC39_U_diff_in_B_2 NetR15_U_diff_in_B_2 NetR17_U_diff_in_B_2 NetR18_U_diff_in_B_1 NetR19_U_diff_in_B_1 NetU10_U_diff_in_B_15
net class U10_U_diff_in_A_Nets: +15 -15 GND NetC37_U_diff_in_A_2 NetC38_U_diff_in_A_1 NetC38_U_diff_in_A_2 NetC39_U_diff_in_A_1 NetC39_U_diff_in_A_2 NetR15_U_diff_in_A_2 NetR17_U_diff_in_A_2 NetR18_U_diff_in_A_1 NetR19_U_diff_in_A_1 NetU10_U_diff_in_A_15
net class U9_24dB_d_Nets: +15 -15 NetC25_24dB_d_2 NetC27_24dB_d_1 NetC27_24dB_d_2 NetR11_24dB_d_1
net class U9_24dB_c_Nets: +15 -15 NetC25_24dB_c_2 NetC27_24dB_c_1 NetC27_24dB_c_2 NetR11_24dB_c_1
net class U9_24dB_b_Nets: +15 -15 NetC25_24dB_b_2 NetC27_24dB_b_1 NetC27_24dB_b_2 NetR11_24dB_b_1
net class U9_24dB_a_Nets: +15 -15 NetC25_24dB_a_2 NetC27_24dB_a_1 NetC27_24dB_a_2 NetR11_24dB_a_1
net class U9_12dB_d_Nets: +15 -15 NetC25_12dB_d_2 NetC27_12dB_d_1 NetC27_12dB_d_2 NetR11_12dB_d_1
net class U9_12dB_c_Nets: +15 -15 NetC25_12dB_c_2 NetC27_12dB_c_1 NetC27_12dB_c_2 NetR11_12dB_c_1
net class U9_12dB_b_Nets: +15 -15 NetC25_12dB_b_2 NetC27_12dB_b_1 NetC27_12dB_b_2 NetR11_12dB_b_1
net class U9_12dB_a_Nets: +15 -15 NetC25_12dB_a_2 NetC27_12dB_a_1 NetC27_12dB_a_2 NetR11_12dB_a_1
net class U9_6dB_d_Nets: +15 -15 NetC25_6dB_d_2 NetC27_6dB_d_1 NetC27_6dB_d_2 NetR11_6dB_d_1
net class U9_6dB_c_Nets: +15 -15 NetC25_6dB_c_2 NetC27_6dB_c_1 NetC27_6dB_c_2 NetR11_6dB_c_1
net class U9_6dB_b_Nets: +15 -15 NetC25_6dB_b_2 NetC27_6dB_b_1 NetC27_6dB_b_2 NetR11_6dB_b_1
net class U9_6dB_a_Nets: +15 -15 NetC25_6dB_a_2 NetC27_6dB_a_1 NetC27_6dB_a_2 NetR11_6dB_a_1
net class U9_3dB_d_Nets: +15 -15 NetC25_3dB_d_2 NetC27_3dB_d_1 NetC27_3dB_d_2 NetR11_3dB_d_1
net class U9_3dB_c_Nets: +15 -15 NetC25_3dB_c_2 NetC27_3dB_c_1 NetC27_3dB_c_2 NetR11_3dB_c_1
net class U9_3dB_b_Nets: +15 -15 NetC25_3dB_b_2 NetC27_3dB_b_1 NetC27_3dB_b_2 NetR11_3dB_b_1
net class U9_3dB_a_Nets: +15 -15 NetC25_3dB_a_2 NetC27_3dB_a_1 NetC27_3dB_a_2 NetR11_3dB_a_1
net class U8_24dB_d_Nets: D1 GND NetC27_24dB_d_1 NetC39_U_diff_in_D_2 NetD6_24dB_d_1 NetD7_24dB_d_2 NetR11_24dB_d_1 NetU8_12dB_d_4 NetU8_24dB_d_7 NetU8_24dB_d_8 NetU8_24dB_d_14 NetU8_24dB_d_15 NetU8_24dB_d_16
net class U8_24dB_c_Nets: C1 GND NetC27_24dB_c_1 NetC39_U_diff_in_C_2 NetD6_24dB_c_1 NetD7_24dB_c_2 NetR11_24dB_c_1 NetU8_12dB_c_4 NetU8_24dB_c_7 NetU8_24dB_c_8 NetU8_24dB_c_14 NetU8_24dB_c_15 NetU8_24dB_c_16
net class U8_24dB_b_Nets: B1 GND NetC27_24dB_b_1 NetC39_U_diff_in_B_2 NetD6_24dB_b_1 NetD7_24dB_b_2 NetR11_24dB_b_1 NetU8_12dB_b_4 NetU8_24dB_b_7 NetU8_24dB_b_8 NetU8_24dB_b_14 NetU8_24dB_b_15 NetU8_24dB_b_16
net class U8_24dB_a_Nets: A1 GND NetC27_24dB_a_1 NetC39_U_diff_in_A_2 NetD6_24dB_a_1 NetD7_24dB_a_2 NetR11_24dB_a_1 NetU8_12dB_a_4 NetU8_24dB_a_7 NetU8_24dB_a_8 NetU8_24dB_a_14 NetU8_24dB_a_15 NetU8_24dB_a_16
net class U8_12dB_d_Nets: D2 GND NetC27_12dB_d_1 NetD6_12dB_d_1 NetD7_12dB_d_2 NetR11_12dB_d_1 NetU8_6dB_d_4 NetU8_12dB_d_4 NetU8_12dB_d_7 NetU8_12dB_d_8 NetU8_12dB_d_14 NetU8_12dB_d_15 NetU8_12dB_d_16
net class U8_12dB_c_Nets: C2 GND NetC27_12dB_c_1 NetD6_12dB_c_1 NetD7_12dB_c_2 NetR11_12dB_c_1 NetU8_6dB_c_4 NetU8_12dB_c_4 NetU8_12dB_c_7 NetU8_12dB_c_8 NetU8_12dB_c_14 NetU8_12dB_c_15 NetU8_12dB_c_16
net class U8_12dB_b_Nets: B2 GND NetC27_12dB_b_1 NetD6_12dB_b_1 NetD7_12dB_b_2 NetR11_12dB_b_1 NetU8_6dB_b_4 NetU8_12dB_b_4 NetU8_12dB_b_7 NetU8_12dB_b_8 NetU8_12dB_b_14 NetU8_12dB_b_15 NetU8_12dB_b_16
net class U8_12dB_a_Nets: A2 GND NetC27_12dB_a_1 NetD6_12dB_a_1 NetD7_12dB_a_2 NetR11_12dB_a_1 NetU8_6dB_a_4 NetU8_12dB_a_4 NetU8_12dB_a_7 NetU8_12dB_a_8 NetU8_12dB_a_14 NetU8_12dB_a_15 NetU8_12dB_a_16
net class U8_6dB_d_Nets: D3 GND NetC27_6dB_d_1 NetD6_6dB_d_1 NetD7_6dB_d_2 NetR11_6dB_d_1 NetU8_3dB_d_4 NetU8_6dB_d_4 NetU8_6dB_d_7 NetU8_6dB_d_8 NetU8_6dB_d_14 NetU8_6dB_d_15 NetU8_6dB_d_16
net class U8_6dB_c_Nets: C3 GND NetC27_6dB_c_1 NetD6_6dB_c_1 NetD7_6dB_c_2 NetR11_6dB_c_1 NetU8_3dB_c_4 NetU8_6dB_c_4 NetU8_6dB_c_7 NetU8_6dB_c_8 NetU8_6dB_c_14 NetU8_6dB_c_15 NetU8_6dB_c_16
net class U8_6dB_b_Nets: B3 GND NetC27_6dB_b_1 NetD6_6dB_b_1 NetD7_6dB_b_2 NetR11_6dB_b_1 NetU8_3dB_b_4 NetU8_6dB_b_4 NetU8_6dB_b_7 NetU8_6dB_b_8 NetU8_6dB_b_14 NetU8_6dB_b_15 NetU8_6dB_b_16
net class U8_6dB_a_Nets: A3 GND NetC27_6dB_a_1 NetD6_6dB_a_1 NetD7_6dB_a_2 NetR11_6dB_a_1 NetU8_3dB_a_4 NetU8_6dB_a_4 NetU8_6dB_a_7 NetU8_6dB_a_8 NetU8_6dB_a_14 NetU8_6dB_a_15 NetU8_6dB_a_16
net class U8_3dB_d_Nets: D4 GND NetC27_3dB_d_1 NetD6_3dB_d_1 NetD7_3dB_d_2 NetR11_3dB_d_1 NetTP21_1 NetU8_3dB_d_4 NetU8_3dB_d_7 NetU8_3dB_d_8 NetU8_3dB_d_14 NetU8_3dB_d_15 NetU8_3dB_d_16
net class U8_3dB_c_Nets: C4 GND NetC27_3dB_c_1 NetD6_3dB_c_1 NetD7_3dB_c_2 NetR11_3dB_c_1 NetTP18_1 NetU8_3dB_c_4 NetU8_3dB_c_7 NetU8_3dB_c_8 NetU8_3dB_c_14 NetU8_3dB_c_15 NetU8_3dB_c_16
net class U8_3dB_b_Nets: B4 GND NetC27_3dB_b_1 NetD6_3dB_b_1 NetD7_3dB_b_2 NetR11_3dB_b_1 NetTP15_1 NetU8_3dB_b_4 NetU8_3dB_b_7 NetU8_3dB_b_8 NetU8_3dB_b_14 NetU8_3dB_b_15 NetU8_3dB_b_16
net class U8_3dB_a_Nets: A4 GND NetC27_3dB_a_1 NetD6_3dB_a_1 NetD7_3dB_a_2 NetR11_3dB_a_1 NetTP2_1 NetU8_3dB_a_4 NetU8_3dB_a_7 NetU8_3dB_a_8 NetU8_3dB_a_14 NetU8_3dB_a_15 NetU8_3dB_a_16
net class U7_Nets: +15 GND VCC
net class U6_Nets: +15 -15 NetC16_2 NetR6_1 NetR6_2 NetTP22_1
net class U5_Nets: +15 -15 NetC13_2 NetR5_1 NetR5_2 NetTP19_1
net class U4_Nets: +15 -15 NetC10_2 NetR4_1 NetR4_2 NetTP16_1
net class U3_Nets: +15 -15 NetC7_2 NetR3_1 NetR3_2 NetTP13_1
net class U2_PZ3_d_Nets: D7 GND NetC4_PZ3_d_2 NetD1_PZ3_d_1 NetD2_PZ3_d_2 NetR30_PZ3_d_1 NetTP22_1 NetU2_PZ3_d_4
net class U2_PZ3_c_Nets: C7 GND NetC4_PZ3_c_2 NetD1_PZ3_c_1 NetD2_PZ3_c_2 NetR30_PZ3_c_1 NetTP19_1 NetU2_PZ3_c_4
net class U2_PZ3_b_Nets: B7 GND NetC4_PZ3_b_2 NetD1_PZ3_b_1 NetD2_PZ3_b_2 NetR30_PZ3_b_1 NetTP16_1 NetU2_PZ3_b_4
net class U2_PZ3_a_Nets: A7 GND NetC4_PZ3_a_2 NetD1_PZ3_a_1 NetD2_PZ3_a_2 NetR30_PZ3_a_1 NetTP13_1 NetU2_PZ3_a_4
net class U2_PZ2_d_Nets: D6 GND NetC4_PZ2_d_2 NetD1_PZ2_d_1 NetD2_PZ2_d_2 NetR30_PZ2_d_1 NetU2_PZ2_d_4 NetU2_PZ3_d_4
net class U2_PZ2_c_Nets: C6 GND NetC4_PZ2_c_2 NetD1_PZ2_c_1 NetD2_PZ2_c_2 NetR30_PZ2_c_1 NetU2_PZ2_c_4 NetU2_PZ3_c_4
net class U2_PZ2_b_Nets: B6 GND NetC4_PZ2_b_2 NetD1_PZ2_b_1 NetD2_PZ2_b_2 NetR30_PZ2_b_1 NetU2_PZ2_b_4 NetU2_PZ3_b_4
net class U2_PZ2_a_Nets: A6 GND NetC4_PZ2_a_2 NetD1_PZ2_a_1 NetD2_PZ2_a_2 NetR30_PZ2_a_1 NetU2_PZ2_a_4 NetU2_PZ3_a_4
net class U2_PZ1_d_Nets: D5 GND NetC4_PZ1_d_2 NetD1_PZ1_d_1 NetD2_PZ1_d_2 NetR30_PZ1_d_1 NetTP21_1 NetU2_PZ2_d_4
net class U2_PZ1_c_Nets: C5 GND NetC4_PZ1_c_2 NetD1_PZ1_c_1 NetD2_PZ1_c_2 NetR30_PZ1_c_1 NetTP18_1 NetU2_PZ2_c_4
net class U2_PZ1_b_Nets: B5 GND NetC4_PZ1_b_2 NetD1_PZ1_b_1 NetD2_PZ1_b_2 NetR30_PZ1_b_1 NetTP15_1 NetU2_PZ2_b_4
net class U2_PZ1_a_Nets: A5 GND NetC4_PZ1_a_2 NetD1_PZ1_a_1 NetD2_PZ1_a_2 NetR30_PZ1_a_1 NetTP2_1 NetU2_PZ2_a_4
net class U1_PZ3_d_Nets: +15 -15 NetC2_PZ3_d_2 NetC4_PZ3_d_1 NetC4_PZ3_d_2 NetR30_PZ3_d_1
net class U1_PZ3_c_Nets: +15 -15 NetC2_PZ3_c_2 NetC4_PZ3_c_1 NetC4_PZ3_c_2 NetR30_PZ3_c_1
net class U1_PZ3_b_Nets: +15 -15 NetC2_PZ3_b_2 NetC4_PZ3_b_1 NetC4_PZ3_b_2 NetR30_PZ3_b_1
net class U1_PZ3_a_Nets: +15 -15 NetC2_PZ3_a_2 NetC4_PZ3_a_1 NetC4_PZ3_a_2 NetR30_PZ3_a_1
net class U1_PZ2_d_Nets: +15 -15 NetC2_PZ2_d_2 NetC4_PZ2_d_1 NetC4_PZ2_d_2 NetR30_PZ2_d_1
net class U1_PZ2_c_Nets: +15 -15 NetC2_PZ2_c_2 NetC4_PZ2_c_1 NetC4_PZ2_c_2 NetR30_PZ2_c_1
net class U1_PZ2_b_Nets: +15 -15 NetC2_PZ2_b_2 NetC4_PZ2_b_1 NetC4_PZ2_b_2 NetR30_PZ2_b_1
net class U1_PZ2_a_Nets: +15 -15 NetC2_PZ2_a_2 NetC4_PZ2_a_1 NetC4_PZ2_a_2 NetR30_PZ2_a_1
net class U1_PZ1_d_Nets: +15 -15 NetC2_PZ1_d_2 NetC4_PZ1_d_1 NetC4_PZ1_d_2 NetR30_PZ1_d_1
net class U1_PZ1_c_Nets: +15 -15 NetC2_PZ1_c_2 NetC4_PZ1_c_1 NetC4_PZ1_c_2 NetR30_PZ1_c_1
net class U1_PZ1_b_Nets: +15 -15 NetC2_PZ1_b_2 NetC4_PZ1_b_1 NetC4_PZ1_b_2 NetR30_PZ1_b_1
net class U1_PZ1_a_Nets: +15 -15 NetC2_PZ1_a_2 NetC4_PZ1_a_1 NetC4_PZ1_a_2 NetR30_PZ1_a_1
net class TP22_Nets: NetTP22_1
net class TP21_Nets: NetTP21_1
net class TP20_Nets: NetC39_U_diff_in_D_2
net class TP19_Nets: NetTP19_1
net class TP18_Nets: NetTP18_1
net class TP17_Nets: NetC39_U_diff_in_C_2
net class TP16_Nets: NetTP16_1
net class TP15_Nets: NetTP15_1
net class TP14_Nets: NetC39_U_diff_in_B_2
net class TP13_Nets: NetTP13_1
net class TP12_Nets: GND
net class TP11_Nets: GND
net class TP10_Nets: GND
net class TP9_U_diff_out_D_Nets: NetR26_U_diff_out_D_1
net class TP9_U_diff_out_C_Nets: NetR26_U_diff_out_C_1
net class TP9_U_diff_out_B_Nets: NetR26_U_diff_out_B_1
net class TP9_U_diff_out_A_Nets: NetR26_U_diff_out_A_1
net class TP9_Nets: GND
net class TP8_U_diff_out_D_Nets: NetR6_2
net class TP8_U_diff_out_C_Nets: NetR5_2
net class TP8_U_diff_out_B_Nets: NetR4_2
net class TP8_U_diff_out_A_Nets: NetR3_2
net class TP7_U_diff_out_D_Nets: NetR23_U_diff_out_D_1
net class TP7_U_diff_out_C_Nets: NetR23_U_diff_out_C_1
net class TP7_U_diff_out_B_Nets: NetR23_U_diff_out_B_1
net class TP7_U_diff_out_A_Nets: NetR23_U_diff_out_A_1
net class TP6_Nets: -15
net class TP5_Nets: VCC
net class TP4_Nets: GND
net class TP3_Nets: +15
net class TP2_Nets: NetTP2_1
net class TP1_Nets: NetC39_U_diff_in_A_2
net class R33_U_diff_in_D_Nets: AN_4 NetC38_U_diff_in_D_1
net class R33_U_diff_in_C_Nets: AN_3 NetC38_U_diff_in_C_1
net class R33_U_diff_in_B_Nets: AN_2 NetC38_U_diff_in_B_1
net class R33_U_diff_in_A_Nets: AN_1 NetC38_U_diff_in_A_1
net class R32_U_diff_in_D_Nets: AP_4 NetC38_U_diff_in_D_2
net class R32_U_diff_in_C_Nets: AP_3 NetC38_U_diff_in_C_2
net class R32_U_diff_in_B_Nets: AP_2 NetC38_U_diff_in_B_2
net class R32_U_diff_in_A_Nets: AP_1 NetC38_U_diff_in_A_2
net class R31_U_logic_D_Nets: BO_24 BO_25 BO_26 BO_27 BO_28 BO_29 BO_30 BO_31 NetR31_U_logic_D_1 NetR31_U_logic_D_2 NetR31_U_logic_D_3 NetR31_U_logic_D_4 NetR31_U_logic_D_5 NetR31_U_logic_D_6 NetR31_U_logic_D_7 NetR31_U_logic_D_8
net class R31_U_logic_C_Nets: BO_16 BO_17 BO_18 BO_19 BO_20 BO_21 BO_22 BO_23 NetR31_U_logic_C_1 NetR31_U_logic_C_2 NetR31_U_logic_C_3 NetR31_U_logic_C_4 NetR31_U_logic_C_5 NetR31_U_logic_C_6 NetR31_U_logic_C_7 NetR31_U_logic_C_8
net class R31_U_logic_B_Nets: BO_8 BO_9 BO_10 BO_11 BO_12 BO_13 BO_14 BO_15 NetR31_U_logic_B_1 NetR31_U_logic_B_2 NetR31_U_logic_B_3 NetR31_U_logic_B_4 NetR31_U_logic_B_5 NetR31_U_logic_B_6 NetR31_U_logic_B_7 NetR31_U_logic_B_8
net class R31_U_logic_A_Nets: BO_0 BO_1 BO_2 BO_3 BO_4 BO_5 BO_6 BO_7 NetR31_U_logic_A_1 NetR31_U_logic_A_2 NetR31_U_logic_A_3 NetR31_U_logic_A_4 NetR31_U_logic_A_5 NetR31_U_logic_A_6 NetR31_U_logic_A_7 NetR31_U_logic_A_8
net class R30_PZ3_d_Nets: GND NetR30_PZ3_d_1
net class R30_PZ3_c_Nets: GND NetR30_PZ3_c_1
net class R30_PZ3_b_Nets: GND NetR30_PZ3_b_1
net class R30_PZ3_a_Nets: GND NetR30_PZ3_a_1
net class R30_PZ2_d_Nets: GND NetR30_PZ2_d_1
net class R30_PZ2_c_Nets: GND NetR30_PZ2_c_1
net class R30_PZ2_b_Nets: GND NetR30_PZ2_b_1
net class R30_PZ2_a_Nets: GND NetR30_PZ2_a_1
net class R30_PZ1_d_Nets: GND NetR30_PZ1_d_1
net class R30_PZ1_c_Nets: GND NetR30_PZ1_c_1
net class R30_PZ1_b_Nets: GND NetR30_PZ1_b_1
net class R30_PZ1_a_Nets: GND NetR30_PZ1_a_1
net class R29_U_logic_D_Nets: BI_24 BI_25 BI_26 BI_27 BI_28 BI_29 BI_30 BI_31 VCC
net class R29_U_logic_C_Nets: BI_16 BI_17 BI_18 BI_19 BI_20 BI_21 BI_22 BI_23 VCC
net class R29_U_logic_B_Nets: BI_8 BI_9 BI_10 BI_11 BI_12 BI_13 BI_14 BI_15 VCC
net class R29_U_logic_A_Nets: BI_0 BI_1 BI_2 BI_3 BI_4 BI_5 BI_6 BI_7 VCC
net class R28_U_diff_out_D_Nets: NetR26_U_diff_out_D_1 NetR27_U_diff_out_D_2
net class R28_U_diff_out_C_Nets: NetR26_U_diff_out_C_1 NetR27_U_diff_out_C_2
net class R28_U_diff_out_B_Nets: NetR26_U_diff_out_B_1 NetR27_U_diff_out_B_2
net class R28_U_diff_out_A_Nets: NetR26_U_diff_out_A_1 NetR27_U_diff_out_A_2
net class R27_U_diff_out_D_Nets: NetR6_2 NetR27_U_diff_out_D_2
net class R27_U_diff_out_C_Nets: NetR5_2 NetR27_U_diff_out_C_2
net class R27_U_diff_out_B_Nets: NetR4_2 NetR27_U_diff_out_B_2
net class R27_U_diff_out_A_Nets: NetR3_2 NetR27_U_diff_out_A_2
net class R26_U_diff_out_D_Nets: NetR26_U_diff_out_D_1 WN4
net class R26_U_diff_out_C_Nets: NetR26_U_diff_out_C_1 WN3
net class R26_U_diff_out_B_Nets: NetR26_U_diff_out_B_1 WN2
net class R26_U_diff_out_A_Nets: NetR26_U_diff_out_A_1 WN1
net class R25_U_diff_out_D_Nets: NetR23_U_diff_out_D_1 NetR24_U_diff_out_D_2
net class R25_U_diff_out_C_Nets: NetR23_U_diff_out_C_1 NetR24_U_diff_out_C_2
net class R25_U_diff_out_B_Nets: NetR23_U_diff_out_B_1 NetR24_U_diff_out_B_2
net class R25_U_diff_out_A_Nets: NetR23_U_diff_out_A_1 NetR24_U_diff_out_A_2
net class R24_U_diff_out_D_Nets: NetR6_2 NetR24_U_diff_out_D_2
net class R24_U_diff_out_C_Nets: NetR5_2 NetR24_U_diff_out_C_2
net class R24_U_diff_out_B_Nets: NetR4_2 NetR24_U_diff_out_B_2
net class R24_U_diff_out_A_Nets: NetR3_2 NetR24_U_diff_out_A_2
net class R23_U_diff_out_D_Nets: NetR23_U_diff_out_D_1 WP4
net class R23_U_diff_out_C_Nets: NetR23_U_diff_out_C_1 WP3
net class R23_U_diff_out_B_Nets: NetR23_U_diff_out_B_1 WP2
net class R23_U_diff_out_A_Nets: NetR23_U_diff_out_A_1 WP1
net class R22_U_diff_in_D_Nets: AN_4 GND
net class R22_U_diff_in_C_Nets: AN_3 GND
net class R22_U_diff_in_B_Nets: AN_2 GND
net class R22_U_diff_in_A_Nets: AN_1 GND
net class R21_U_diff_in_D_Nets: NetC39_U_diff_in_D_1 NetR19_U_diff_in_D_1
net class R21_U_diff_in_C_Nets: NetC39_U_diff_in_C_1 NetR19_U_diff_in_C_1
net class R21_U_diff_in_B_Nets: NetC39_U_diff_in_B_1 NetR19_U_diff_in_B_1
net class R21_U_diff_in_A_Nets: NetC39_U_diff_in_A_1 NetR19_U_diff_in_A_1
net class R20_U_diff_in_D_Nets: NetC39_U_diff_in_D_1 NetC39_U_diff_in_D_2
net class R20_U_diff_in_C_Nets: NetC39_U_diff_in_C_1 NetC39_U_diff_in_C_2
net class R20_U_diff_in_B_Nets: NetC39_U_diff_in_B_1 NetC39_U_diff_in_B_2
net class R20_U_diff_in_A_Nets: NetC39_U_diff_in_A_1 NetC39_U_diff_in_A_2
net class R19_U_diff_in_D_Nets: NetR18_U_diff_in_D_1 NetR19_U_diff_in_D_1
net class R19_U_diff_in_C_Nets: NetR18_U_diff_in_C_1 NetR19_U_diff_in_C_1
net class R19_U_diff_in_B_Nets: NetR18_U_diff_in_B_1 NetR19_U_diff_in_B_1
net class R19_U_diff_in_A_Nets: NetR18_U_diff_in_A_1 NetR19_U_diff_in_A_1
net class R18_U_diff_in_D_Nets: NetR17_U_diff_in_D_2 NetR18_U_diff_in_D_1
net class R18_U_diff_in_C_Nets: NetR17_U_diff_in_C_2 NetR18_U_diff_in_C_1
net class R18_U_diff_in_B_Nets: NetR17_U_diff_in_B_2 NetR18_U_diff_in_B_1
net class R18_U_diff_in_A_Nets: NetR17_U_diff_in_A_2 NetR18_U_diff_in_A_1
net class R17_U_diff_in_D_Nets: NetR15_U_diff_in_D_2 NetR17_U_diff_in_D_2
net class R17_U_diff_in_C_Nets: NetR15_U_diff_in_C_2 NetR17_U_diff_in_C_2
net class R17_U_diff_in_B_Nets: NetR15_U_diff_in_B_2 NetR17_U_diff_in_B_2
net class R17_U_diff_in_A_Nets: NetR15_U_diff_in_A_2 NetR17_U_diff_in_A_2
net class R16_U_diff_in_D_Nets: GND NetC37_U_diff_in_D_2
net class R16_U_diff_in_C_Nets: GND NetC37_U_diff_in_C_2
net class R16_U_diff_in_B_Nets: GND NetC37_U_diff_in_B_2
net class R16_U_diff_in_A_Nets: GND NetC37_U_diff_in_A_2
net class R15_U_diff_in_D_Nets: NetC37_U_diff_in_D_2 NetR15_U_diff_in_D_2
net class R15_U_diff_in_C_Nets: NetC37_U_diff_in_C_2 NetR15_U_diff_in_C_2
net class R15_U_diff_in_B_Nets: NetC37_U_diff_in_B_2 NetR15_U_diff_in_B_2
net class R15_U_diff_in_A_Nets: NetC37_U_diff_in_A_2 NetR15_U_diff_in_A_2
net class R14_U_diff_in_D_Nets: AP_4 GND
net class R14_U_diff_in_C_Nets: AP_3 GND
net class R14_U_diff_in_B_Nets: AP_2 GND
net class R14_U_diff_in_A_Nets: AP_1 GND
net class R13_24dB_d_Nets: NetC27_24dB_d_1 NetC27_24dB_d_2
net class R13_24dB_c_Nets: NetC27_24dB_c_1 NetC27_24dB_c_2
net class R13_24dB_b_Nets: NetC27_24dB_b_1 NetC27_24dB_b_2
net class R13_24dB_a_Nets: NetC27_24dB_a_1 NetC27_24dB_a_2
net class R13_12dB_d_Nets: NetC27_12dB_d_1 NetC27_12dB_d_2
net class R13_12dB_c_Nets: NetC27_12dB_c_1 NetC27_12dB_c_2
net class R13_12dB_b_Nets: NetC27_12dB_b_1 NetC27_12dB_b_2
net class R13_12dB_a_Nets: NetC27_12dB_a_1 NetC27_12dB_a_2
net class R13_6dB_d_Nets: NetC27_6dB_d_1 NetC27_6dB_d_2
net class R13_6dB_c_Nets: NetC27_6dB_c_1 NetC27_6dB_c_2
net class R13_6dB_b_Nets: NetC27_6dB_b_1 NetC27_6dB_b_2
net class R13_6dB_a_Nets: NetC27_6dB_a_1 NetC27_6dB_a_2
net class R13_3dB_d_Nets: NetC27_3dB_d_1 NetC27_3dB_d_2
net class R13_3dB_c_Nets: NetC27_3dB_c_1 NetC27_3dB_c_2
net class R13_3dB_b_Nets: NetC27_3dB_b_1 NetC27_3dB_b_2
net class R13_3dB_a_Nets: NetC27_3dB_a_1 NetC27_3dB_a_2
net class R12_24dB_d_Nets: GND NetC27_24dB_d_2
net class R12_24dB_c_Nets: GND NetC27_24dB_c_2
net class R12_24dB_b_Nets: GND NetC27_24dB_b_2
net class R12_24dB_a_Nets: GND NetC27_24dB_a_2
net class R12_12dB_d_Nets: GND NetC27_12dB_d_2
net class R12_12dB_c_Nets: GND NetC27_12dB_c_2
net class R12_12dB_b_Nets: GND NetC27_12dB_b_2
net class R12_12dB_a_Nets: GND NetC27_12dB_a_2
net class R12_6dB_d_Nets: GND NetC27_6dB_d_2
net class R12_6dB_c_Nets: GND NetC27_6dB_c_2
net class R12_6dB_b_Nets: GND NetC27_6dB_b_2
net class R12_6dB_a_Nets: GND NetC27_6dB_a_2
net class R12_3dB_d_Nets: GND NetC27_3dB_d_2
net class R12_3dB_c_Nets: GND NetC27_3dB_c_2
net class R12_3dB_b_Nets: GND NetC27_3dB_b_2
net class R12_3dB_a_Nets: GND NetC27_3dB_a_2
net class R11_24dB_d_Nets: GND NetR11_24dB_d_1
net class R11_24dB_c_Nets: GND NetR11_24dB_c_1
net class R11_24dB_b_Nets: GND NetR11_24dB_b_1
net class R11_24dB_a_Nets: GND NetR11_24dB_a_1
net class R11_12dB_d_Nets: GND NetR11_12dB_d_1
net class R11_12dB_c_Nets: GND NetR11_12dB_c_1
net class R11_12dB_b_Nets: GND NetR11_12dB_b_1
net class R11_12dB_a_Nets: GND NetR11_12dB_a_1
net class R11_6dB_d_Nets: GND NetR11_6dB_d_1
net class R11_6dB_c_Nets: GND NetR11_6dB_c_1
net class R11_6dB_b_Nets: GND NetR11_6dB_b_1
net class R11_6dB_a_Nets: GND NetR11_6dB_a_1
net class R11_3dB_d_Nets: GND NetR11_3dB_d_1
net class R11_3dB_c_Nets: GND NetR11_3dB_c_1
net class R11_3dB_b_Nets: GND NetR11_3dB_b_1
net class R11_3dB_a_Nets: GND NetR11_3dB_a_1
net class R10_Nets: +15 NetD4_1
net class R9_Nets: -15 NetD4_4
net class R8_Nets: -15 NetJ5_7
net class R7_Nets: +15 NetJ5_6
net class R6_Nets: NetR6_1 NetR6_2
net class R5_Nets: NetR5_1 NetR5_2
net class R4_Nets: NetR4_1 NetR4_2
net class R3_Nets: NetR3_1 NetR3_2
net class R2_PZ3_d_Nets: NetC4_PZ3_d_1 NetC5_PZ3_d_1
net class R2_PZ3_c_Nets: NetC4_PZ3_c_1 NetC5_PZ3_c_1
net class R2_PZ3_b_Nets: NetC4_PZ3_b_1 NetC5_PZ3_b_1
net class R2_PZ3_a_Nets: NetC4_PZ3_a_1 NetC5_PZ3_a_1
net class R2_PZ2_d_Nets: NetC4_PZ2_d_1 NetC5_PZ2_d_1
net class R2_PZ2_c_Nets: NetC4_PZ2_c_1 NetC5_PZ2_c_1
net class R2_PZ2_b_Nets: NetC4_PZ2_b_1 NetC5_PZ2_b_1
net class R2_PZ2_a_Nets: NetC4_PZ2_a_1 NetC5_PZ2_a_1
net class R2_PZ1_d_Nets: NetC4_PZ1_d_1 NetC5_PZ1_d_1
net class R2_PZ1_c_Nets: NetC4_PZ1_c_1 NetC5_PZ1_c_1
net class R2_PZ1_b_Nets: NetC4_PZ1_b_1 NetC5_PZ1_b_1
net class R2_PZ1_a_Nets: NetC4_PZ1_a_1 NetC5_PZ1_a_1
net class R1_PZ3_d_Nets: NetC4_PZ3_d_1 NetC4_PZ3_d_2
net class R1_PZ3_c_Nets: NetC4_PZ3_c_1 NetC4_PZ3_c_2
net class R1_PZ3_b_Nets: NetC4_PZ3_b_1 NetC4_PZ3_b_2
net class R1_PZ3_a_Nets: NetC4_PZ3_a_1 NetC4_PZ3_a_2
net class R1_PZ2_d_Nets: NetC4_PZ2_d_1 NetC4_PZ2_d_2
net class R1_PZ2_c_Nets: NetC4_PZ2_c_1 NetC4_PZ2_c_2
net class R1_PZ2_b_Nets: NetC4_PZ2_b_1 NetC4_PZ2_b_2
net class R1_PZ2_a_Nets: NetC4_PZ2_a_1 NetC4_PZ2_a_2
net class R1_PZ1_d_Nets: NetC4_PZ1_d_1 NetC4_PZ1_d_2
net class R1_PZ1_c_Nets: NetC4_PZ1_c_1 NetC4_PZ1_c_2
net class R1_PZ1_b_Nets: NetC4_PZ1_b_1 NetC4_PZ1_b_2
net class R1_PZ1_a_Nets: NetC4_PZ1_a_1 NetC4_PZ1_a_2
net class P4_Nets: GND NetL1_1 NetL2_1
net class P3_Nets: BO_0 BO_1 BO_2 BO_3 BO_4 BO_5 BO_6 BO_7 BO_8 BO_9 BO_10 BO_11 BO_12 BO_13 BO_14 BO_15 BO_16 BO_17 BO_18 BO_19 BO_20 BO_21 BO_22 BO_23 BO_24 BO_25 BO_26 BO_27 BO_28 BO_29 BO_30 BO_31 NetL7_1 NetL8_1 NetP3_1 NetP3_19 NetP3_20
net class P2_Nets: +15 BI_0 BI_1 BI_2 BI_3 BI_4 BI_5 BI_6 BI_7 BI_8 BI_9 BI_10 BI_11 BI_12 BI_13 BI_14 BI_15 BI_16 BI_17 BI_18 BI_19 BI_20 BI_21 BI_22 BI_23 BI_24 BI_25 BI_26 BI_27 BI_28 BI_29 BI_30 BI_31 GND NetP2_37 NetP2_38 NetP2_39 NetP2_40
net class P1_Nets: BI_0 BI_1 BI_2 BI_3 BI_4 BI_5 BI_6 BI_7 BI_8 BI_9 BI_10 BI_11 BI_12 BI_13 BI_14 BI_15 BI_16 BI_17 BI_18 BI_19 BI_20 BI_21 BI_22 BI_23 BI_24 BI_25 BI_26 BI_27 BI_28 BI_29 BI_30 BI_31 GND NetL5_1 NetL6_1 NetP1_19
net class L8_Nets: +15 NetL8_1
net class L7_Nets: +15 NetL7_1
net class L6_Nets: +15 NetL6_1
net class L5_Nets: +15 NetL5_1
net class L2_Nets: -15 NetL2_1
net class L1_Nets: +15 NetL1_1
net class J5_Nets: AN_1 AN_2 AN_3 AN_4 AP_1 AP_2 AP_3 AP_4 GND NetC34_2 NetJ2_5 NetJ5_6 NetJ5_7 NetJ5_8 NetJ5_13
net class J6_Nets: NetC35_2 NetJ1_5 WN1 WN2 WN3 WN4 WP1 WP2 WP3 WP4
net class D7_24dB_d_Nets: +15 NetD7_24dB_d_2
net class D7_24dB_c_Nets: +15 NetD7_24dB_c_2
net class D7_24dB_b_Nets: +15 NetD7_24dB_b_2
net class D7_24dB_a_Nets: +15 NetD7_24dB_a_2
net class D7_12dB_d_Nets: +15 NetD7_12dB_d_2
net class D7_12dB_c_Nets: +15 NetD7_12dB_c_2
net class D7_12dB_b_Nets: +15 NetD7_12dB_b_2
net class D7_12dB_a_Nets: +15 NetD7_12dB_a_2
net class D7_6dB_d_Nets: +15 NetD7_6dB_d_2
net class D7_6dB_c_Nets: +15 NetD7_6dB_c_2
net class D7_6dB_b_Nets: +15 NetD7_6dB_b_2
net class D7_6dB_a_Nets: +15 NetD7_6dB_a_2
net class D7_3dB_d_Nets: +15 NetD7_3dB_d_2
net class D7_3dB_c_Nets: +15 NetD7_3dB_c_2
net class D7_3dB_b_Nets: +15 NetD7_3dB_b_2
net class D7_3dB_a_Nets: +15 NetD7_3dB_a_2
net class D6_24dB_d_Nets: -15 NetD6_24dB_d_1
net class D6_24dB_c_Nets: -15 NetD6_24dB_c_1
net class D6_24dB_b_Nets: -15 NetD6_24dB_b_1
net class D6_24dB_a_Nets: -15 NetD6_24dB_a_1
net class D6_12dB_d_Nets: -15 NetD6_12dB_d_1
net class D6_12dB_c_Nets: -15 NetD6_12dB_c_1
net class D6_12dB_b_Nets: -15 NetD6_12dB_b_1
net class D6_12dB_a_Nets: -15 NetD6_12dB_a_1
net class D6_6dB_d_Nets: -15 NetD6_6dB_d_1
net class D6_6dB_c_Nets: -15 NetD6_6dB_c_1
net class D6_6dB_b_Nets: -15 NetD6_6dB_b_1
net class D6_6dB_a_Nets: -15 NetD6_6dB_a_1
net class D6_3dB_d_Nets: -15 NetD6_3dB_d_1
net class D6_3dB_c_Nets: -15 NetD6_3dB_c_1
net class D6_3dB_b_Nets: -15 NetD6_3dB_b_1
net class D6_3dB_a_Nets: -15 NetD6_3dB_a_1
net class D5_Nets: GND VCC
net class D4_Nets: GND NetD4_1 NetD4_4
net class D3_Nets: +15 VCC
net class D2_PZ3_d_Nets: +15 NetD2_PZ3_d_2
net class D2_PZ3_c_Nets: +15 NetD2_PZ3_c_2
net class D2_PZ3_b_Nets: +15 NetD2_PZ3_b_2
net class D2_PZ3_a_Nets: +15 NetD2_PZ3_a_2
net class D2_PZ2_d_Nets: +15 NetD2_PZ2_d_2
net class D2_PZ2_c_Nets: +15 NetD2_PZ2_c_2
net class D2_PZ2_b_Nets: +15 NetD2_PZ2_b_2
net class D2_PZ2_a_Nets: +15 NetD2_PZ2_a_2
net class D2_PZ1_d_Nets: +15 NetD2_PZ1_d_2
net class D2_PZ1_c_Nets: +15 NetD2_PZ1_c_2
net class D2_PZ1_b_Nets: +15 NetD2_PZ1_b_2
net class D2_PZ1_a_Nets: +15 NetD2_PZ1_a_2
net class D1_PZ3_d_Nets: -15 NetD1_PZ3_d_1
net class D1_PZ3_c_Nets: -15 NetD1_PZ3_c_1
net class D1_PZ3_b_Nets: -15 NetD1_PZ3_b_1
net class D1_PZ3_a_Nets: -15 NetD1_PZ3_a_1
net class D1_PZ2_d_Nets: -15 NetD1_PZ2_d_1
net class D1_PZ2_c_Nets: -15 NetD1_PZ2_c_1
net class D1_PZ2_b_Nets: -15 NetD1_PZ2_b_1
net class D1_PZ2_a_Nets: -15 NetD1_PZ2_a_1
net class D1_PZ1_d_Nets: -15 NetD1_PZ1_d_1
net class D1_PZ1_c_Nets: -15 NetD1_PZ1_c_1
net class D1_PZ1_b_Nets: -15 NetD1_PZ1_b_1
net class D1_PZ1_a_Nets: -15 NetD1_PZ1_a_1
net class C39_U_diff_in_D_Nets: NetC39_U_diff_in_D_1 NetC39_U_diff_in_D_2
net class C39_U_diff_in_C_Nets: NetC39_U_diff_in_C_1 NetC39_U_diff_in_C_2
net class C39_U_diff_in_B_Nets: NetC39_U_diff_in_B_1 NetC39_U_diff_in_B_2
net class C39_U_diff_in_A_Nets: NetC39_U_diff_in_A_1 NetC39_U_diff_in_A_2
net class C38_U_diff_in_D_Nets: NetC38_U_diff_in_D_1 NetC38_U_diff_in_D_2
net class C38_U_diff_in_C_Nets: NetC38_U_diff_in_C_1 NetC38_U_diff_in_C_2
net class C38_U_diff_in_B_Nets: NetC38_U_diff_in_B_1 NetC38_U_diff_in_B_2
net class C38_U_diff_in_A_Nets: NetC38_U_diff_in_A_1 NetC38_U_diff_in_A_2
net class C37_U_diff_in_D_Nets: GND NetC37_U_diff_in_D_2
net class C37_U_diff_in_C_Nets: GND NetC37_U_diff_in_C_2
net class C37_U_diff_in_B_Nets: GND NetC37_U_diff_in_B_2
net class C37_U_diff_in_A_Nets: GND NetC37_U_diff_in_A_2
net class C36_U_logic_D_Nets: -15 GND
net class C36_U_logic_C_Nets: -15 GND
net class C36_U_logic_B_Nets: -15 GND
net class C36_U_logic_A_Nets: -15 GND
net class C33_U_logic_D_Nets: GND VCC
net class C33_U_logic_C_Nets: GND VCC
net class C33_U_logic_B_Nets: GND VCC
net class C33_U_logic_A_Nets: GND VCC
net class C32_U_logic_D_Nets: -15 GND
net class C32_U_logic_C_Nets: -15 GND
net class C32_U_logic_B_Nets: -15 GND
net class C32_U_logic_A_Nets: -15 GND
net class C31_U_diff_out_D_Nets: -15 GND
net class C31_U_diff_out_C_Nets: -15 GND
net class C31_U_diff_out_B_Nets: -15 GND
net class C31_U_diff_out_A_Nets: -15 GND
net class C30_U_diff_out_D_Nets: +15 GND
net class C30_U_diff_out_C_Nets: +15 GND
net class C30_U_diff_out_B_Nets: +15 GND
net class C30_U_diff_out_A_Nets: +15 GND
net class C29_U_diff_in_D_Nets: -15 GND
net class C29_U_diff_in_C_Nets: -15 GND
net class C29_U_diff_in_B_Nets: -15 GND
net class C29_U_diff_in_A_Nets: -15 GND
net class C28_U_diff_in_D_Nets: +15 GND
net class C28_U_diff_in_C_Nets: +15 GND
net class C28_U_diff_in_B_Nets: +15 GND
net class C28_U_diff_in_A_Nets: +15 GND
net class C27_24dB_d_Nets: NetC27_24dB_d_1 NetC27_24dB_d_2
net class C27_24dB_c_Nets: NetC27_24dB_c_1 NetC27_24dB_c_2
net class C27_24dB_b_Nets: NetC27_24dB_b_1 NetC27_24dB_b_2
net class C27_24dB_a_Nets: NetC27_24dB_a_1 NetC27_24dB_a_2
net class C27_12dB_d_Nets: NetC27_12dB_d_1 NetC27_12dB_d_2
net class C27_12dB_c_Nets: NetC27_12dB_c_1 NetC27_12dB_c_2
net class C27_12dB_b_Nets: NetC27_12dB_b_1 NetC27_12dB_b_2
net class C27_12dB_a_Nets: NetC27_12dB_a_1 NetC27_12dB_a_2
net class C27_6dB_d_Nets: NetC27_6dB_d_1 NetC27_6dB_d_2
net class C27_6dB_c_Nets: NetC27_6dB_c_1 NetC27_6dB_c_2
net class C27_6dB_b_Nets: NetC27_6dB_b_1 NetC27_6dB_b_2
net class C27_6dB_a_Nets: NetC27_6dB_a_1 NetC27_6dB_a_2
net class C27_3dB_d_Nets: NetC27_3dB_d_1 NetC27_3dB_d_2
net class C27_3dB_c_Nets: NetC27_3dB_c_1 NetC27_3dB_c_2
net class C27_3dB_b_Nets: NetC27_3dB_b_1 NetC27_3dB_b_2
net class C27_3dB_a_Nets: NetC27_3dB_a_1 NetC27_3dB_a_2
net class C26_24dB_d_Nets: +15 GND
net class C26_24dB_c_Nets: +15 GND
net class C26_24dB_b_Nets: +15 GND
net class C26_24dB_a_Nets: +15 GND
net class C26_12dB_d_Nets: +15 GND
net class C26_12dB_c_Nets: +15 GND
net class C26_12dB_b_Nets: +15 GND
net class C26_12dB_a_Nets: +15 GND
net class C26_6dB_d_Nets: +15 GND
net class C26_6dB_c_Nets: +15 GND
net class C26_6dB_b_Nets: +15 GND
net class C26_6dB_a_Nets: +15 GND
net class C26_3dB_d_Nets: +15 GND
net class C26_3dB_c_Nets: +15 GND
net class C26_3dB_b_Nets: +15 GND
net class C26_3dB_a_Nets: +15 GND
net class C25_24dB_d_Nets: GND NetC25_24dB_d_2
net class C25_24dB_c_Nets: GND NetC25_24dB_c_2
net class C25_24dB_b_Nets: GND NetC25_24dB_b_2
net class C25_24dB_a_Nets: GND NetC25_24dB_a_2
net class C25_12dB_d_Nets: GND NetC25_12dB_d_2
net class C25_12dB_c_Nets: GND NetC25_12dB_c_2
net class C25_12dB_b_Nets: GND NetC25_12dB_b_2
net class C25_12dB_a_Nets: GND NetC25_12dB_a_2
net class C25_6dB_d_Nets: GND NetC25_6dB_d_2
net class C25_6dB_c_Nets: GND NetC25_6dB_c_2
net class C25_6dB_b_Nets: GND NetC25_6dB_b_2
net class C25_6dB_a_Nets: GND NetC25_6dB_a_2
net class C25_3dB_d_Nets: GND NetC25_3dB_d_2
net class C25_3dB_c_Nets: GND NetC25_3dB_c_2
net class C25_3dB_b_Nets: GND NetC25_3dB_b_2
net class C25_3dB_a_Nets: GND NetC25_3dB_a_2
net class C24_24dB_d_Nets: -15 GND
net class C24_24dB_c_Nets: -15 GND
net class C24_24dB_b_Nets: -15 GND
net class C24_24dB_a_Nets: -15 GND
net class C24_12dB_d_Nets: -15 GND
net class C24_12dB_c_Nets: -15 GND
net class C24_12dB_b_Nets: -15 GND
net class C24_12dB_a_Nets: -15 GND
net class C24_6dB_d_Nets: -15 GND
net class C24_6dB_c_Nets: -15 GND
net class C24_6dB_b_Nets: -15 GND
net class C24_6dB_a_Nets: -15 GND
net class C24_3dB_d_Nets: -15 GND
net class C24_3dB_c_Nets: -15 GND
net class C24_3dB_b_Nets: -15 GND
net class C24_3dB_a_Nets: -15 GND
net class C23_Nets: -15 GND
net class C22_Nets: -15 GND
net class C21_Nets: GND VCC
net class C20_Nets: +15 GND
net class C19_Nets: +15 GND
net class C18_Nets: +15 GND
net class C17_Nets: +15 GND
net class C16_Nets: GND NetC16_2
net class C15_Nets: -15 GND
net class C14_Nets: +15 GND
net class C13_Nets: GND NetC13_2
net class C12_Nets: -15 GND
net class C11_Nets: +15 GND
net class C10_Nets: GND NetC10_2
net class C9_Nets: -15 GND
net class C8_Nets: +15 GND
net class C7_Nets: GND NetC7_2
net class C6_Nets: -15 GND
net class C5_PZ3_d_Nets: GND NetC5_PZ3_d_1
net class C5_PZ3_c_Nets: GND NetC5_PZ3_c_1
net class C5_PZ3_b_Nets: GND NetC5_PZ3_b_1
net class C5_PZ3_a_Nets: GND NetC5_PZ3_a_1
net class C5_PZ2_d_Nets: GND NetC5_PZ2_d_1
net class C5_PZ2_c_Nets: GND NetC5_PZ2_c_1
net class C5_PZ2_b_Nets: GND NetC5_PZ2_b_1
net class C5_PZ2_a_Nets: GND NetC5_PZ2_a_1
net class C5_PZ1_d_Nets: GND NetC5_PZ1_d_1
net class C5_PZ1_c_Nets: GND NetC5_PZ1_c_1
net class C5_PZ1_b_Nets: GND NetC5_PZ1_b_1
net class C5_PZ1_a_Nets: GND NetC5_PZ1_a_1
net class C4_PZ3_d_Nets: NetC4_PZ3_d_1 NetC4_PZ3_d_2
net class C4_PZ3_c_Nets: NetC4_PZ3_c_1 NetC4_PZ3_c_2
net class C4_PZ3_b_Nets: NetC4_PZ3_b_1 NetC4_PZ3_b_2
net class C4_PZ3_a_Nets: NetC4_PZ3_a_1 NetC4_PZ3_a_2
net class C4_PZ2_d_Nets: NetC4_PZ2_d_1 NetC4_PZ2_d_2
net class C4_PZ2_c_Nets: NetC4_PZ2_c_1 NetC4_PZ2_c_2
net class C4_PZ2_b_Nets: NetC4_PZ2_b_1 NetC4_PZ2_b_2
net class C4_PZ2_a_Nets: NetC4_PZ2_a_1 NetC4_PZ2_a_2
net class C4_PZ1_d_Nets: NetC4_PZ1_d_1 NetC4_PZ1_d_2
net class C4_PZ1_c_Nets: NetC4_PZ1_c_1 NetC4_PZ1_c_2
net class C4_PZ1_b_Nets: NetC4_PZ1_b_1 NetC4_PZ1_b_2
net class C4_PZ1_a_Nets: NetC4_PZ1_a_1 NetC4_PZ1_a_2
net class C3_PZ3_d_Nets: +15 GND
net class C3_PZ3_c_Nets: +15 GND
net class C3_PZ3_b_Nets: +15 GND
net class C3_PZ3_a_Nets: +15 GND
net class C3_PZ2_d_Nets: +15 GND
net class C3_PZ2_c_Nets: +15 GND
net class C3_PZ2_b_Nets: +15 GND
net class C3_PZ2_a_Nets: +15 GND
net class C3_PZ1_d_Nets: +15 GND
net class C3_PZ1_c_Nets: +15 GND
net class C3_PZ1_b_Nets: +15 GND
net class C3_PZ1_a_Nets: +15 GND
net class C2_PZ3_d_Nets: GND NetC2_PZ3_d_2
net class C2_PZ3_c_Nets: GND NetC2_PZ3_c_2
net class C2_PZ3_b_Nets: GND NetC2_PZ3_b_2
net class C2_PZ3_a_Nets: GND NetC2_PZ3_a_2
net class C2_PZ2_d_Nets: GND NetC2_PZ2_d_2
net class C2_PZ2_c_Nets: GND NetC2_PZ2_c_2
net class C2_PZ2_b_Nets: GND NetC2_PZ2_b_2
net class C2_PZ2_a_Nets: GND NetC2_PZ2_a_2
net class C2_PZ1_d_Nets: GND NetC2_PZ1_d_2
net class C2_PZ1_c_Nets: GND NetC2_PZ1_c_2
net class C2_PZ1_b_Nets: GND NetC2_PZ1_b_2
net class C2_PZ1_a_Nets: GND NetC2_PZ1_a_2
net class C1_PZ3_d_Nets: -15 GND
net class C1_PZ3_c_Nets: -15 GND
net class C1_PZ3_b_Nets: -15 GND
net class C1_PZ3_a_Nets: -15 GND
net class C1_PZ2_d_Nets: -15 GND
net class C1_PZ2_c_Nets: -15 GND
net class C1_PZ2_b_Nets: -15 GND
net class C1_PZ2_a_Nets: -15 GND
net class C1_PZ1_d_Nets: -15 GND
net class C1_PZ1_c_Nets: -15 GND
net class C1_PZ1_b_Nets: -15 GND
net class C1_PZ1_a_Nets: -15 GND
net class 24dB_d_Nets: NetC25_24dB_d_2 NetC27_24dB_d_1 NetC27_24dB_d_2 NetD6_24dB_d_1 NetD7_24dB_d_2 NetR11_24dB_d_1 NetU8_24dB_d_7 NetU8_24dB_d_8 NetU8_24dB_d_14 NetU8_24dB_d_15 NetU8_24dB_d_16
net class 24dB_c_Nets: NetC25_24dB_c_2 NetC27_24dB_c_1 NetC27_24dB_c_2 NetD6_24dB_c_1 NetD7_24dB_c_2 NetR11_24dB_c_1 NetU8_24dB_c_7 NetU8_24dB_c_8 NetU8_24dB_c_14 NetU8_24dB_c_15 NetU8_24dB_c_16
net class 24dB_b_Nets: NetC25_24dB_b_2 NetC27_24dB_b_1 NetC27_24dB_b_2 NetD6_24dB_b_1 NetD7_24dB_b_2 NetR11_24dB_b_1 NetU8_24dB_b_7 NetU8_24dB_b_8 NetU8_24dB_b_14 NetU8_24dB_b_15 NetU8_24dB_b_16
net class 24dB_a_Nets: NetC25_24dB_a_2 NetC27_24dB_a_1 NetC27_24dB_a_2 NetD6_24dB_a_1 NetD7_24dB_a_2 NetR11_24dB_a_1 NetU8_24dB_a_7 NetU8_24dB_a_8 NetU8_24dB_a_14 NetU8_24dB_a_15 NetU8_24dB_a_16
net class 12dB_d_Nets: NetC25_12dB_d_2 NetC27_12dB_d_1 NetC27_12dB_d_2 NetD6_12dB_d_1 NetD7_12dB_d_2 NetR11_12dB_d_1 NetU8_12dB_d_7 NetU8_12dB_d_8 NetU8_12dB_d_14 NetU8_12dB_d_15 NetU8_12dB_d_16
net class 12dB_c_Nets: NetC25_12dB_c_2 NetC27_12dB_c_1 NetC27_12dB_c_2 NetD6_12dB_c_1 NetD7_12dB_c_2 NetR11_12dB_c_1 NetU8_12dB_c_7 NetU8_12dB_c_8 NetU8_12dB_c_14 NetU8_12dB_c_15 NetU8_12dB_c_16
net class 12dB_b_Nets: NetC25_12dB_b_2 NetC27_12dB_b_1 NetC27_12dB_b_2 NetD6_12dB_b_1 NetD7_12dB_b_2 NetR11_12dB_b_1 NetU8_12dB_b_7 NetU8_12dB_b_8 NetU8_12dB_b_14 NetU8_12dB_b_15 NetU8_12dB_b_16
net class 12dB_a_Nets: NetC25_12dB_a_2 NetC27_12dB_a_1 NetC27_12dB_a_2 NetD6_12dB_a_1 NetD7_12dB_a_2 NetR11_12dB_a_1 NetU8_12dB_a_7 NetU8_12dB_a_8 NetU8_12dB_a_14 NetU8_12dB_a_15 NetU8_12dB_a_16
net class 6dB_d_Nets: NetC25_6dB_d_2 NetC27_6dB_d_1 NetC27_6dB_d_2 NetD6_6dB_d_1 NetD7_6dB_d_2 NetR11_6dB_d_1 NetU8_6dB_d_7 NetU8_6dB_d_8 NetU8_6dB_d_14 NetU8_6dB_d_15 NetU8_6dB_d_16
net class 6dB_c_Nets: NetC25_6dB_c_2 NetC27_6dB_c_1 NetC27_6dB_c_2 NetD6_6dB_c_1 NetD7_6dB_c_2 NetR11_6dB_c_1 NetU8_6dB_c_7 NetU8_6dB_c_8 NetU8_6dB_c_14 NetU8_6dB_c_15 NetU8_6dB_c_16
net class 6dB_b_Nets: NetC25_6dB_b_2 NetC27_6dB_b_1 NetC27_6dB_b_2 NetD6_6dB_b_1 NetD7_6dB_b_2 NetR11_6dB_b_1 NetU8_6dB_b_7 NetU8_6dB_b_8 NetU8_6dB_b_14 NetU8_6dB_b_15 NetU8_6dB_b_16
net class 6dB_a_Nets: NetC25_6dB_a_2 NetC27_6dB_a_1 NetC27_6dB_a_2 NetD6_6dB_a_1 NetD7_6dB_a_2 NetR11_6dB_a_1 NetU8_6dB_a_7 NetU8_6dB_a_8 NetU8_6dB_a_14 NetU8_6dB_a_15 NetU8_6dB_a_16
net class 3dB_d_Nets: NetC25_3dB_d_2 NetC27_3dB_d_1 NetC27_3dB_d_2 NetD6_3dB_d_1 NetD7_3dB_d_2 NetR11_3dB_d_1 NetU8_3dB_d_7 NetU8_3dB_d_8 NetU8_3dB_d_14 NetU8_3dB_d_15 NetU8_3dB_d_16
net class 3dB_c_Nets: NetC25_3dB_c_2 NetC27_3dB_c_1 NetC27_3dB_c_2 NetD6_3dB_c_1 NetD7_3dB_c_2 NetR11_3dB_c_1 NetU8_3dB_c_7 NetU8_3dB_c_8 NetU8_3dB_c_14 NetU8_3dB_c_15 NetU8_3dB_c_16
net class 3dB_b_Nets: NetC25_3dB_b_2 NetC27_3dB_b_1 NetC27_3dB_b_2 NetD6_3dB_b_1 NetD7_3dB_b_2 NetR11_3dB_b_1 NetU8_3dB_b_7 NetU8_3dB_b_8 NetU8_3dB_b_14 NetU8_3dB_b_15 NetU8_3dB_b_16
net class 3dB_a_Nets: NetC25_3dB_a_2 NetC27_3dB_a_1 NetC27_3dB_a_2 NetD6_3dB_a_1 NetD7_3dB_a_2 NetR11_3dB_a_1 NetU8_3dB_a_7 NetU8_3dB_a_8 NetU8_3dB_a_14 NetU8_3dB_a_15 NetU8_3dB_a_16
component class U_logic_D: C32_U_logic_D C33_U_logic_D C34_U_logic_D C35_U_logic_D C36_U_logic_D R29_U_logic_D R31_U_logic_D U13_U_logic_D U14_U_logic_D U15_U_logic_D
component class U_logic_C: C32_U_logic_C C33_U_logic_C C34_U_logic_C C35_U_logic_C C36_U_logic_C R29_U_logic_C R31_U_logic_C U13_U_logic_C U14_U_logic_C U15_U_logic_C
component class U_logic_B: C32_U_logic_B C33_U_logic_B C34_U_logic_B C35_U_logic_B C36_U_logic_B R29_U_logic_B R31_U_logic_B U13_U_logic_B U14_U_logic_B U15_U_logic_B
component class U_logic_A: C32_U_logic_A C33_U_logic_A C34_U_logic_A C35_U_logic_A C36_U_logic_A R29_U_logic_A R31_U_logic_A U13_U_logic_A U14_U_logic_A U15_U_logic_A
component class PZ3_b: C1_PZ3_b C1_U_83 C2_PZ3_b C2_U_83 C3_PZ3_b C3_U_83 C4_PZ3_b C5_PZ3_b C5_U_83 D1_PZ3_b D1_U_83 D2_PZ3_b D2_U_83 R1_PZ3_b R2_PZ3_b R2_U_83 R3_U_83 R30_PZ3_b U1_PZ3_b U2_PZ3_b
component class PZ3_c: C1_PZ3_c C1_U_82 C2_PZ3_c C2_U_82 C3_PZ3_c C3_U_82 C4_PZ3_c C5_PZ3_c C5_U_82 D1_PZ3_c D1_U_82 D2_PZ3_c D2_U_82 R1_PZ3_c R2_PZ3_c R2_U_82 R3_U_82 R30_PZ3_c U1_PZ3_c U2_PZ3_c
component class PZ3_d: C1_PZ3_d C1_U_81 C2_PZ3_d C2_U_81 C3_PZ3_d C3_U_81 C4_PZ3_d C5_PZ3_d C5_U_81 D1_PZ3_d D1_U_81 D2_PZ3_d D2_U_81 R1_PZ3_d R2_PZ3_d R2_U_81 R3_U_81 R30_PZ3_d U1_PZ3_d U2_PZ3_d
component class PZ2_b: C1_PZ2_b C1_U_73 C2_PZ2_b C2_U_73 C3_PZ2_b C3_U_73 C4_PZ2_b C5_PZ2_b C5_U_73 D1_PZ2_b D1_U_73 D2_PZ2_b D2_U_73 R1_PZ2_b R2_PZ2_b R2_U_73 R3_U_73 R30_PZ2_b U1_PZ2_b U2_PZ2_b
component class PZ2_c: C1_PZ2_c C1_U_72 C2_PZ2_c C2_U_72 C3_PZ2_c C3_U_72 C4_PZ2_c C5_PZ2_c C5_U_72 D1_PZ2_c D1_U_72 D2_PZ2_c D2_U_72 R1_PZ2_c R2_PZ2_c R2_U_72 R3_U_72 R30_PZ2_c U1_PZ2_c U2_PZ2_c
